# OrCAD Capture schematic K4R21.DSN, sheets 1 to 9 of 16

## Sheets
1 P04: ASPEN - Power: size Custom; title: ASPEN-Power; rev: 1.0; note: K4R2 Main
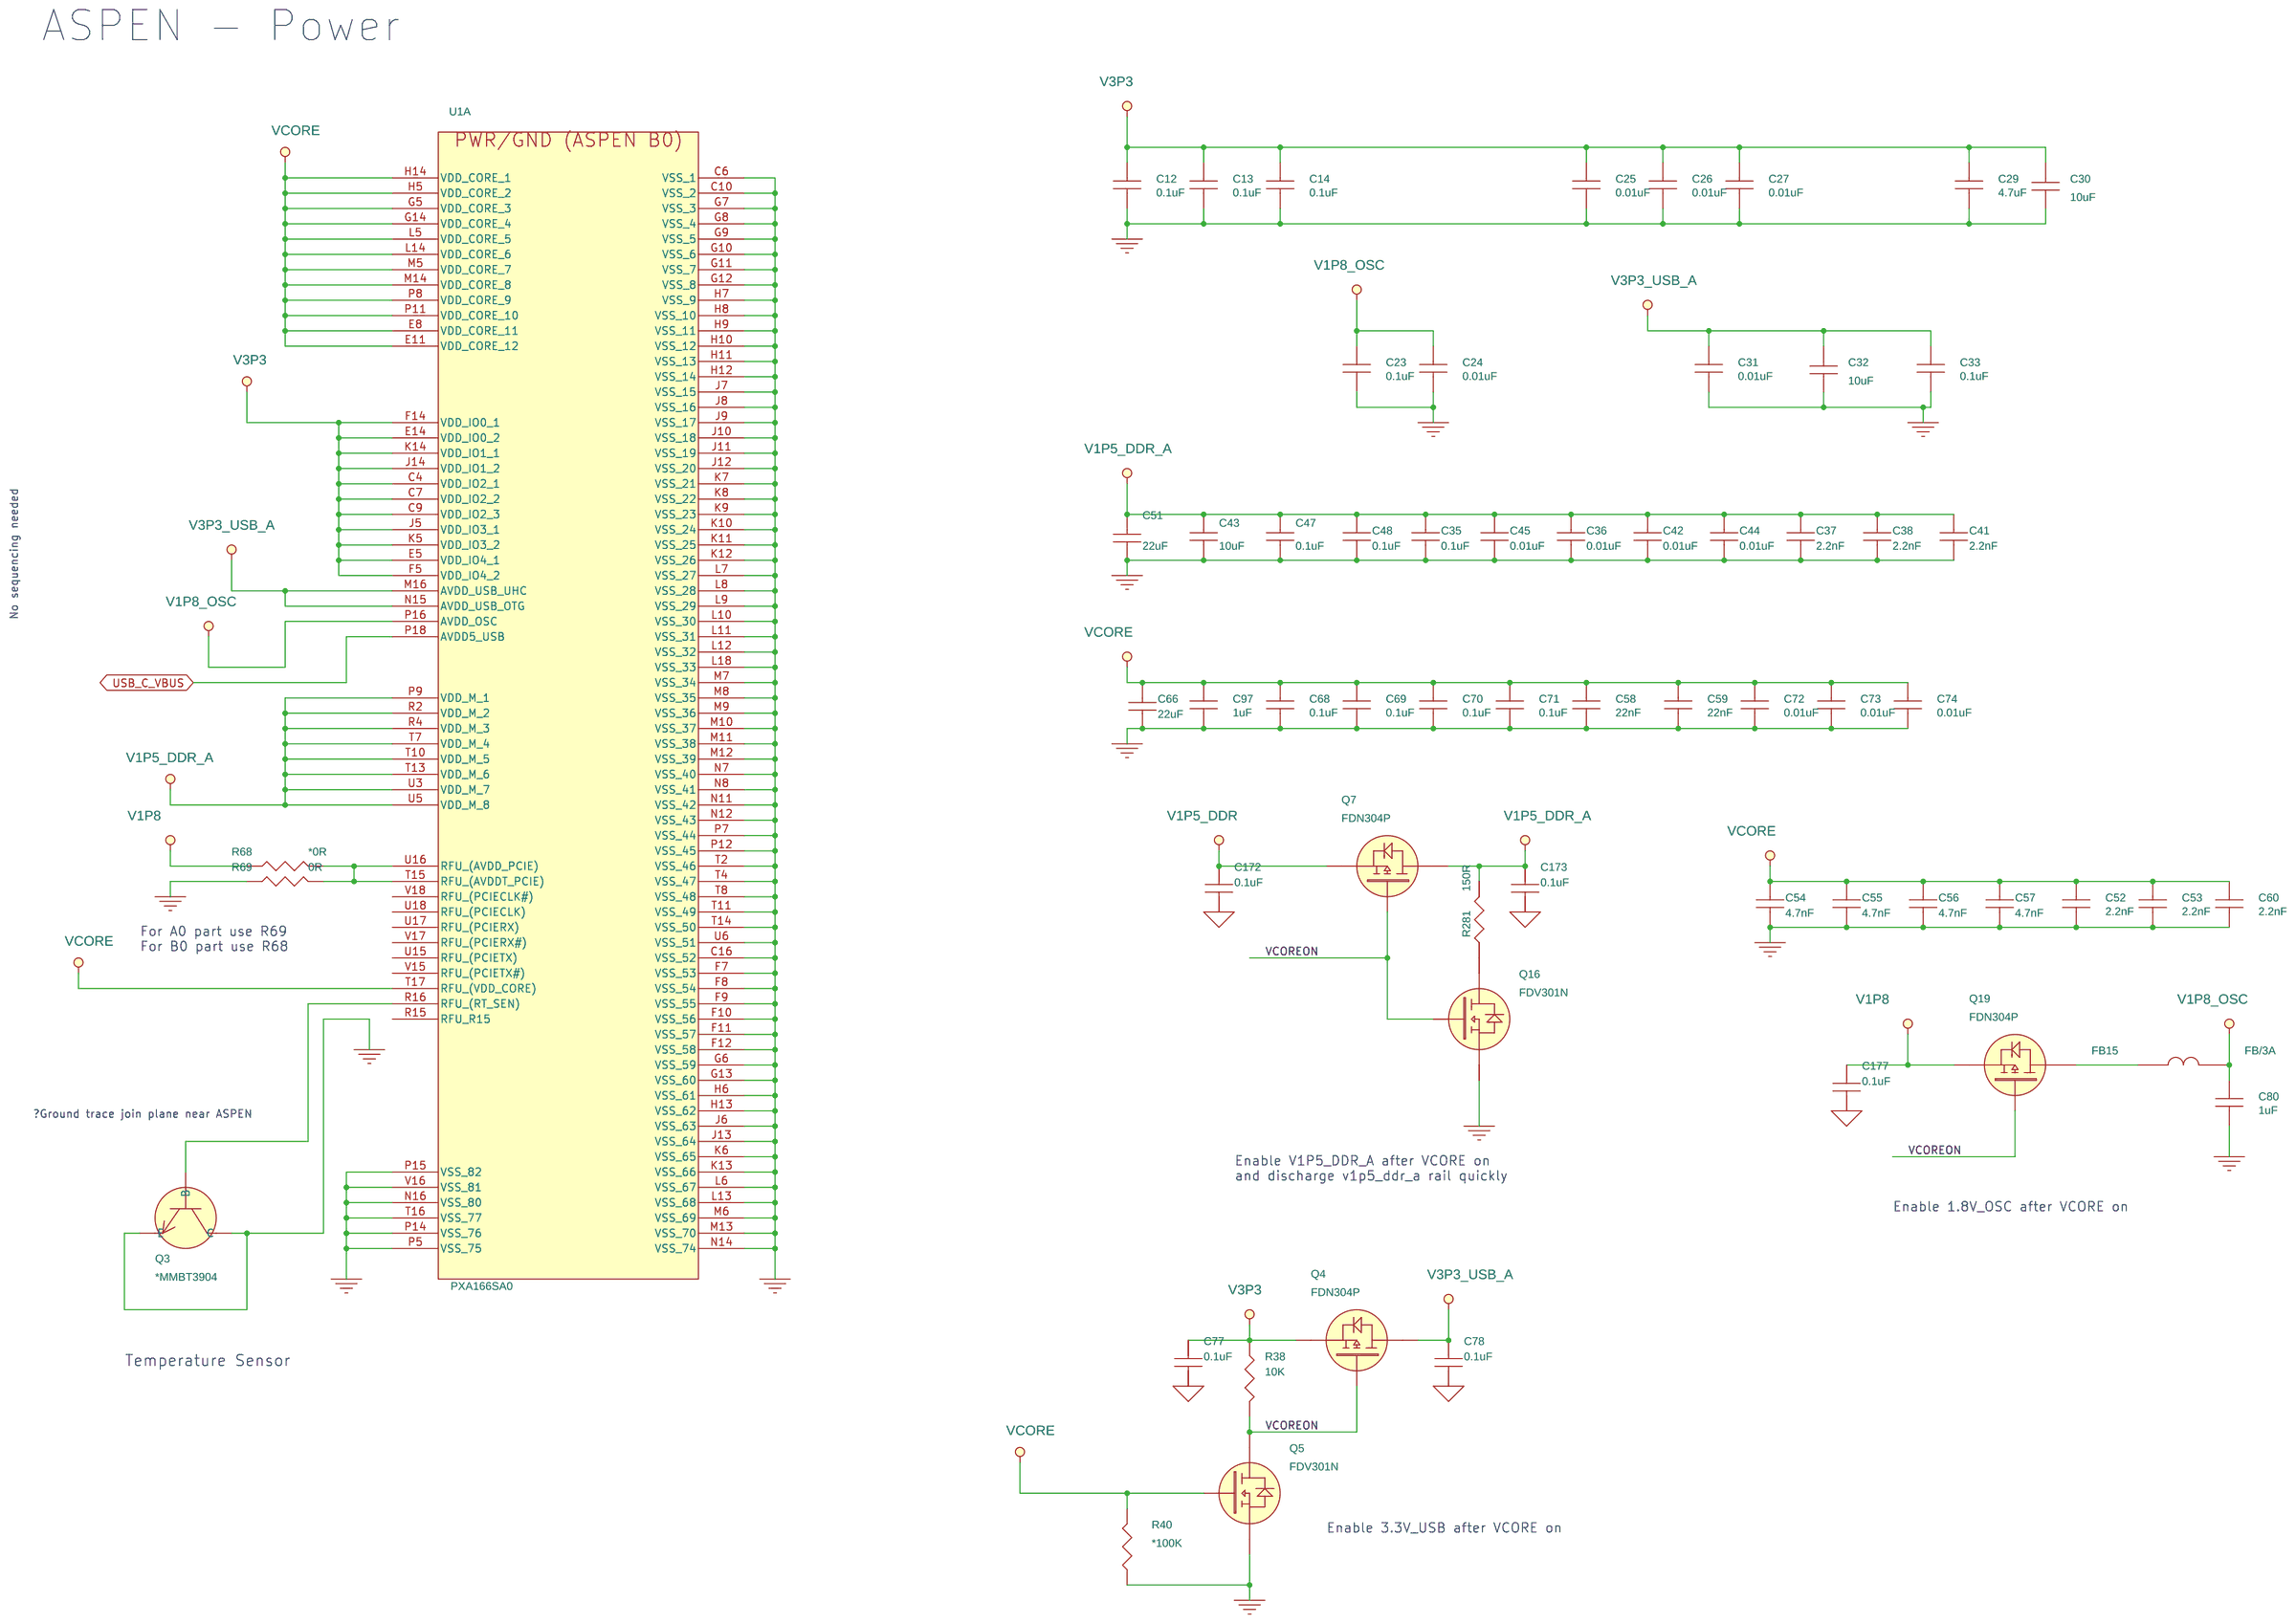
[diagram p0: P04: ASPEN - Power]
2 P06: Wifi 8787: size Custom; title: Wifi
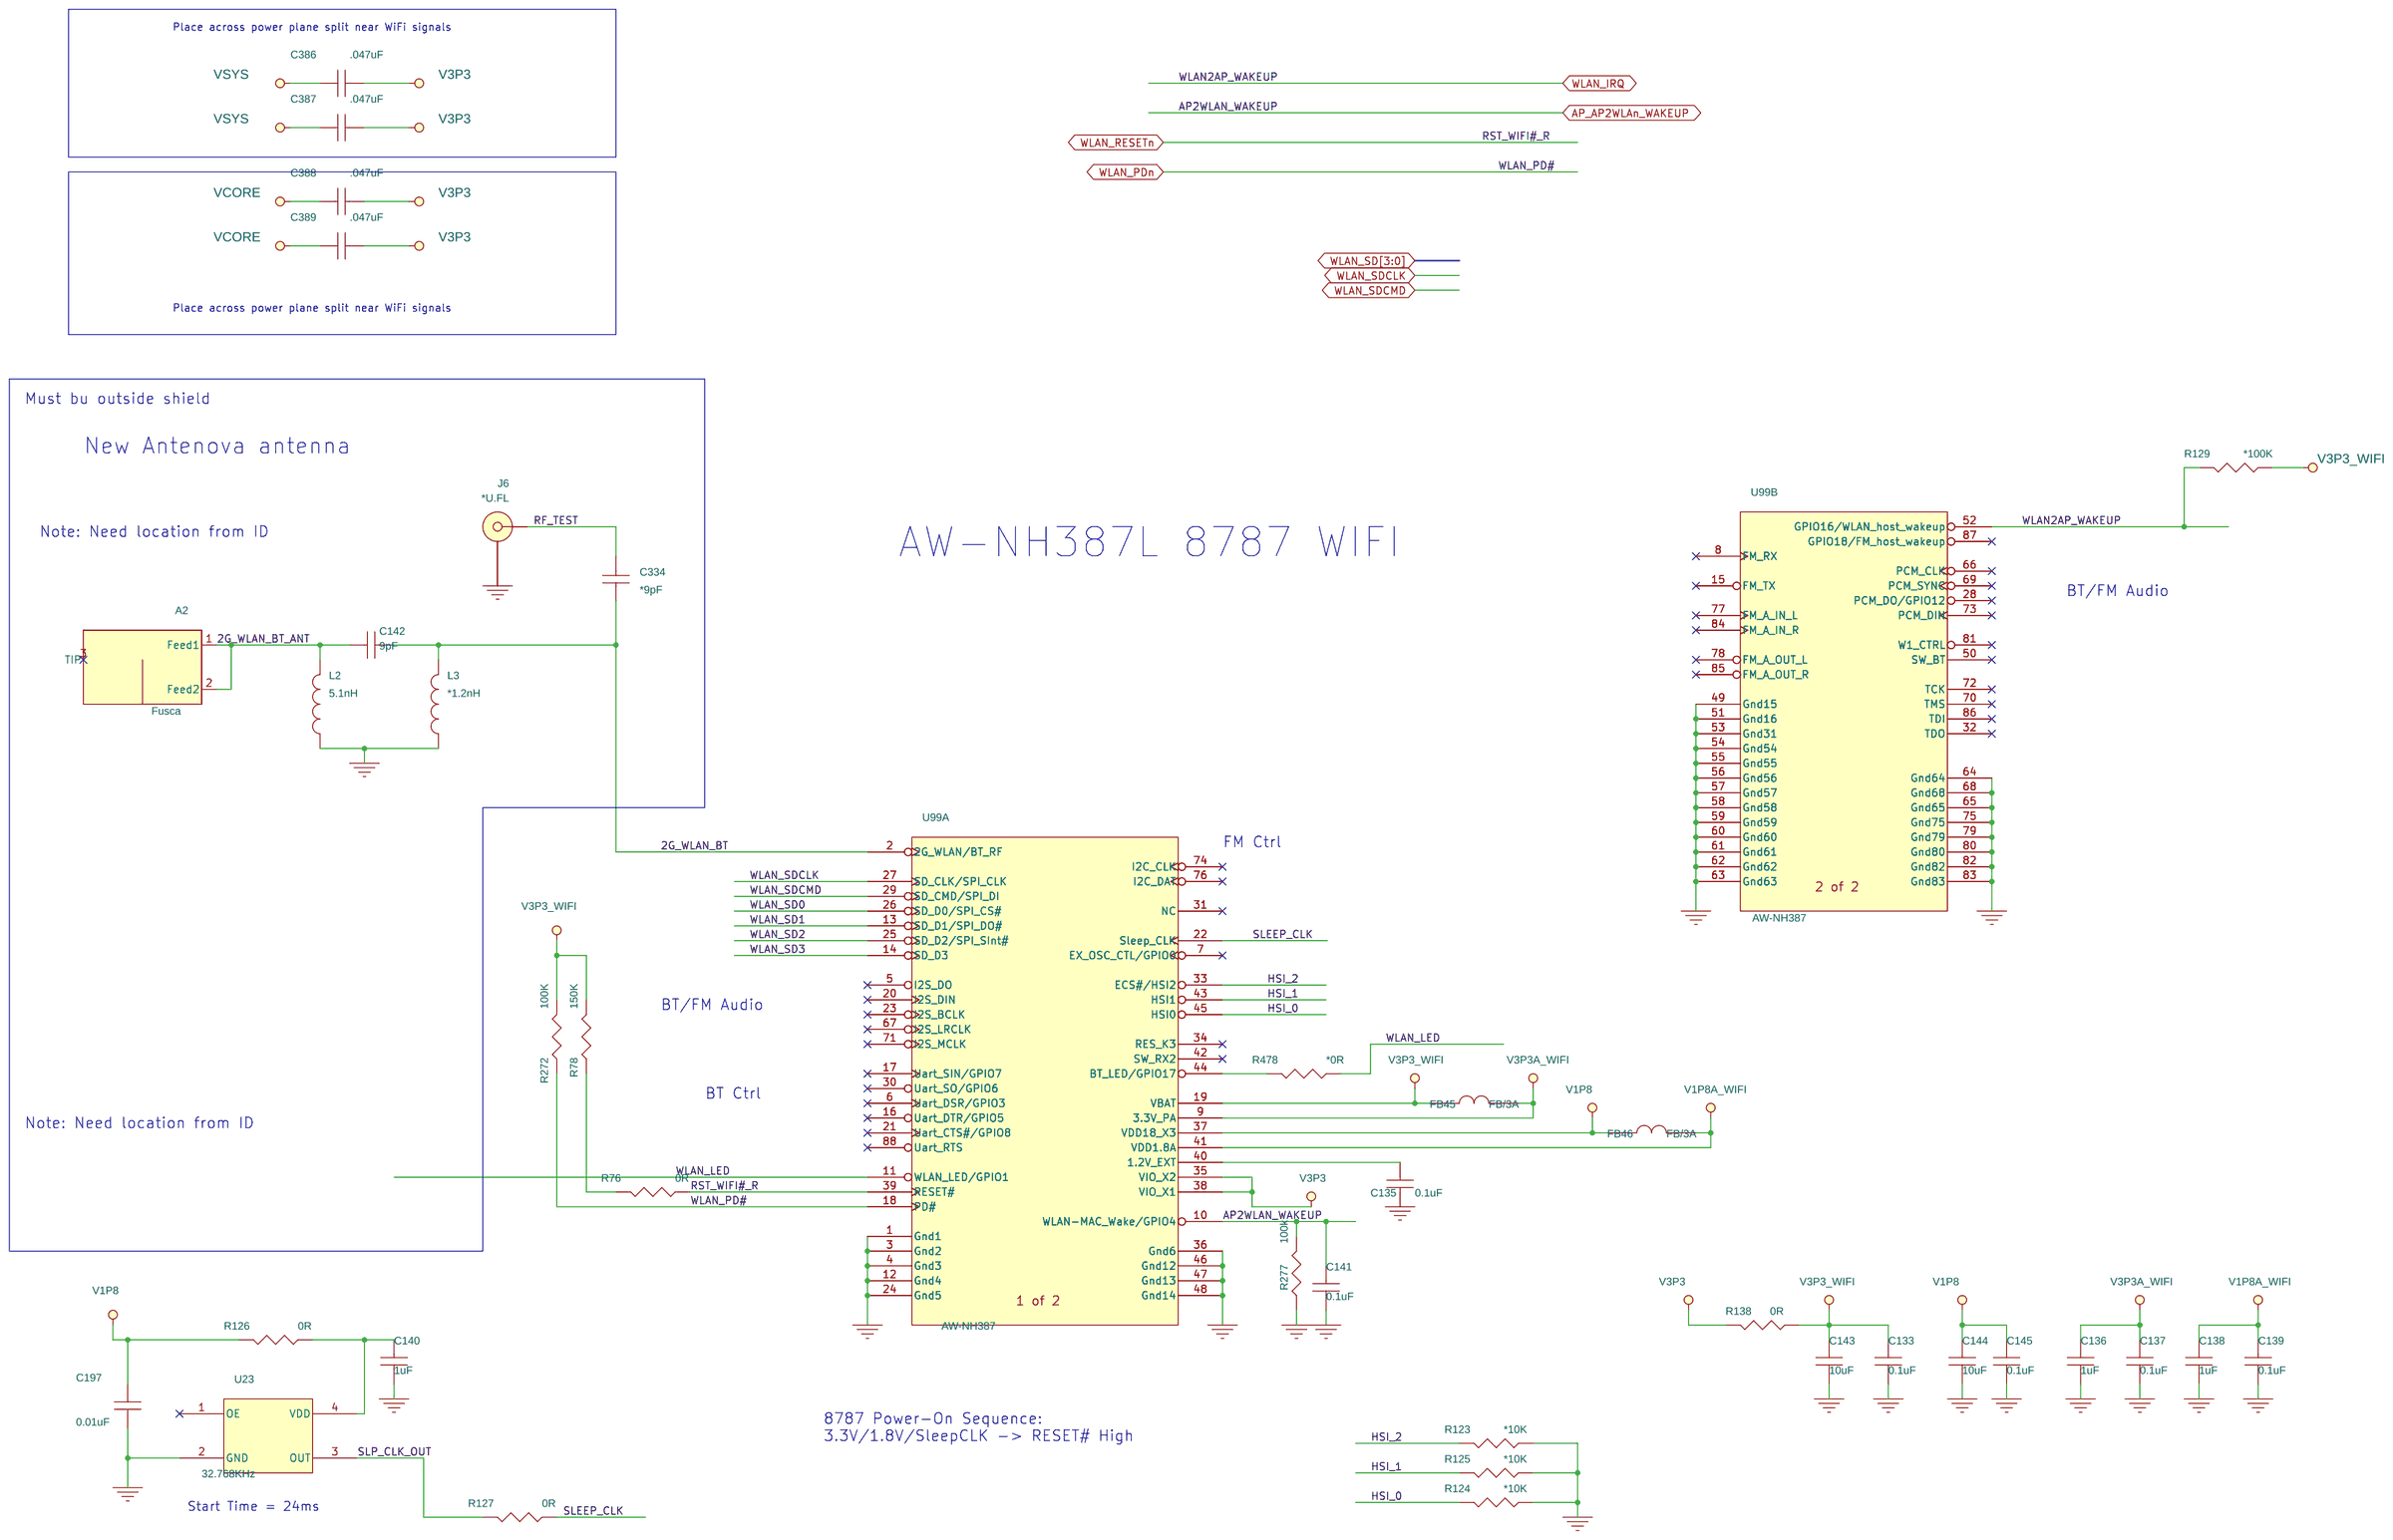
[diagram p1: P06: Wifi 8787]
3 P07: Audio: size Custom; title: Audio; rev: 3.0G
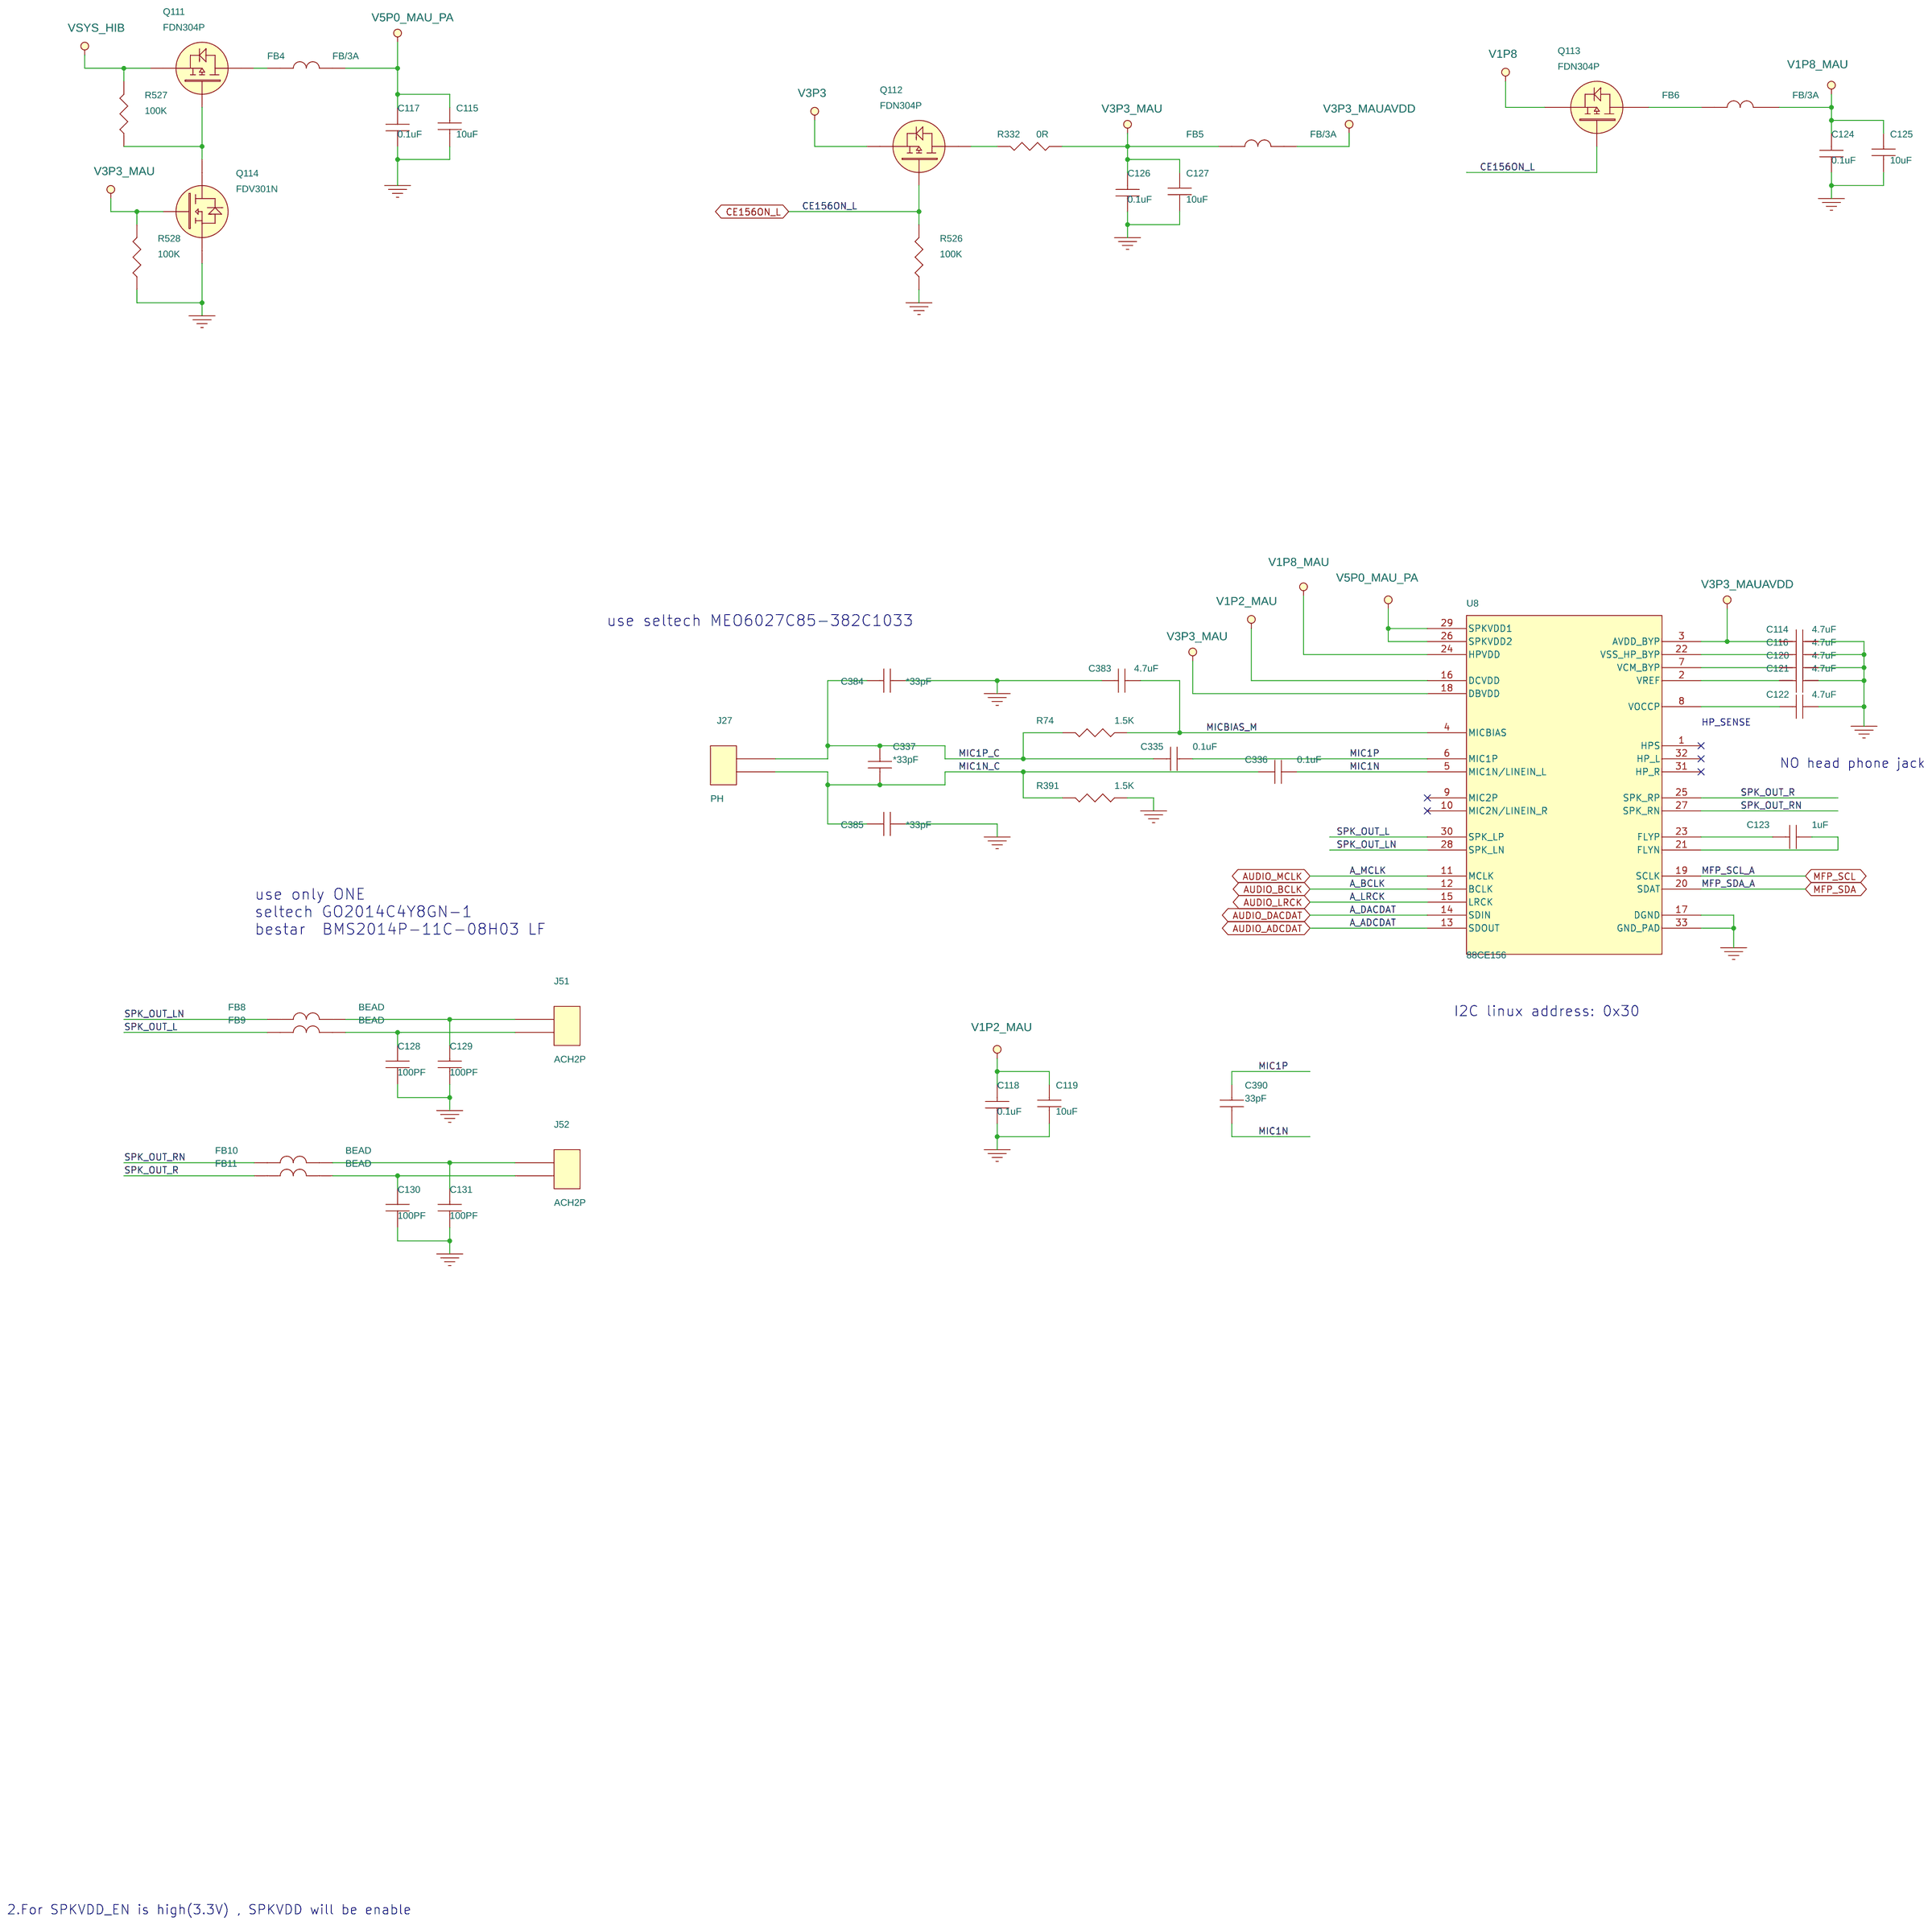
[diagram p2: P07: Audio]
4 P05: DDR3 SPI SD: size Custom; title: DDR3 SDRAM
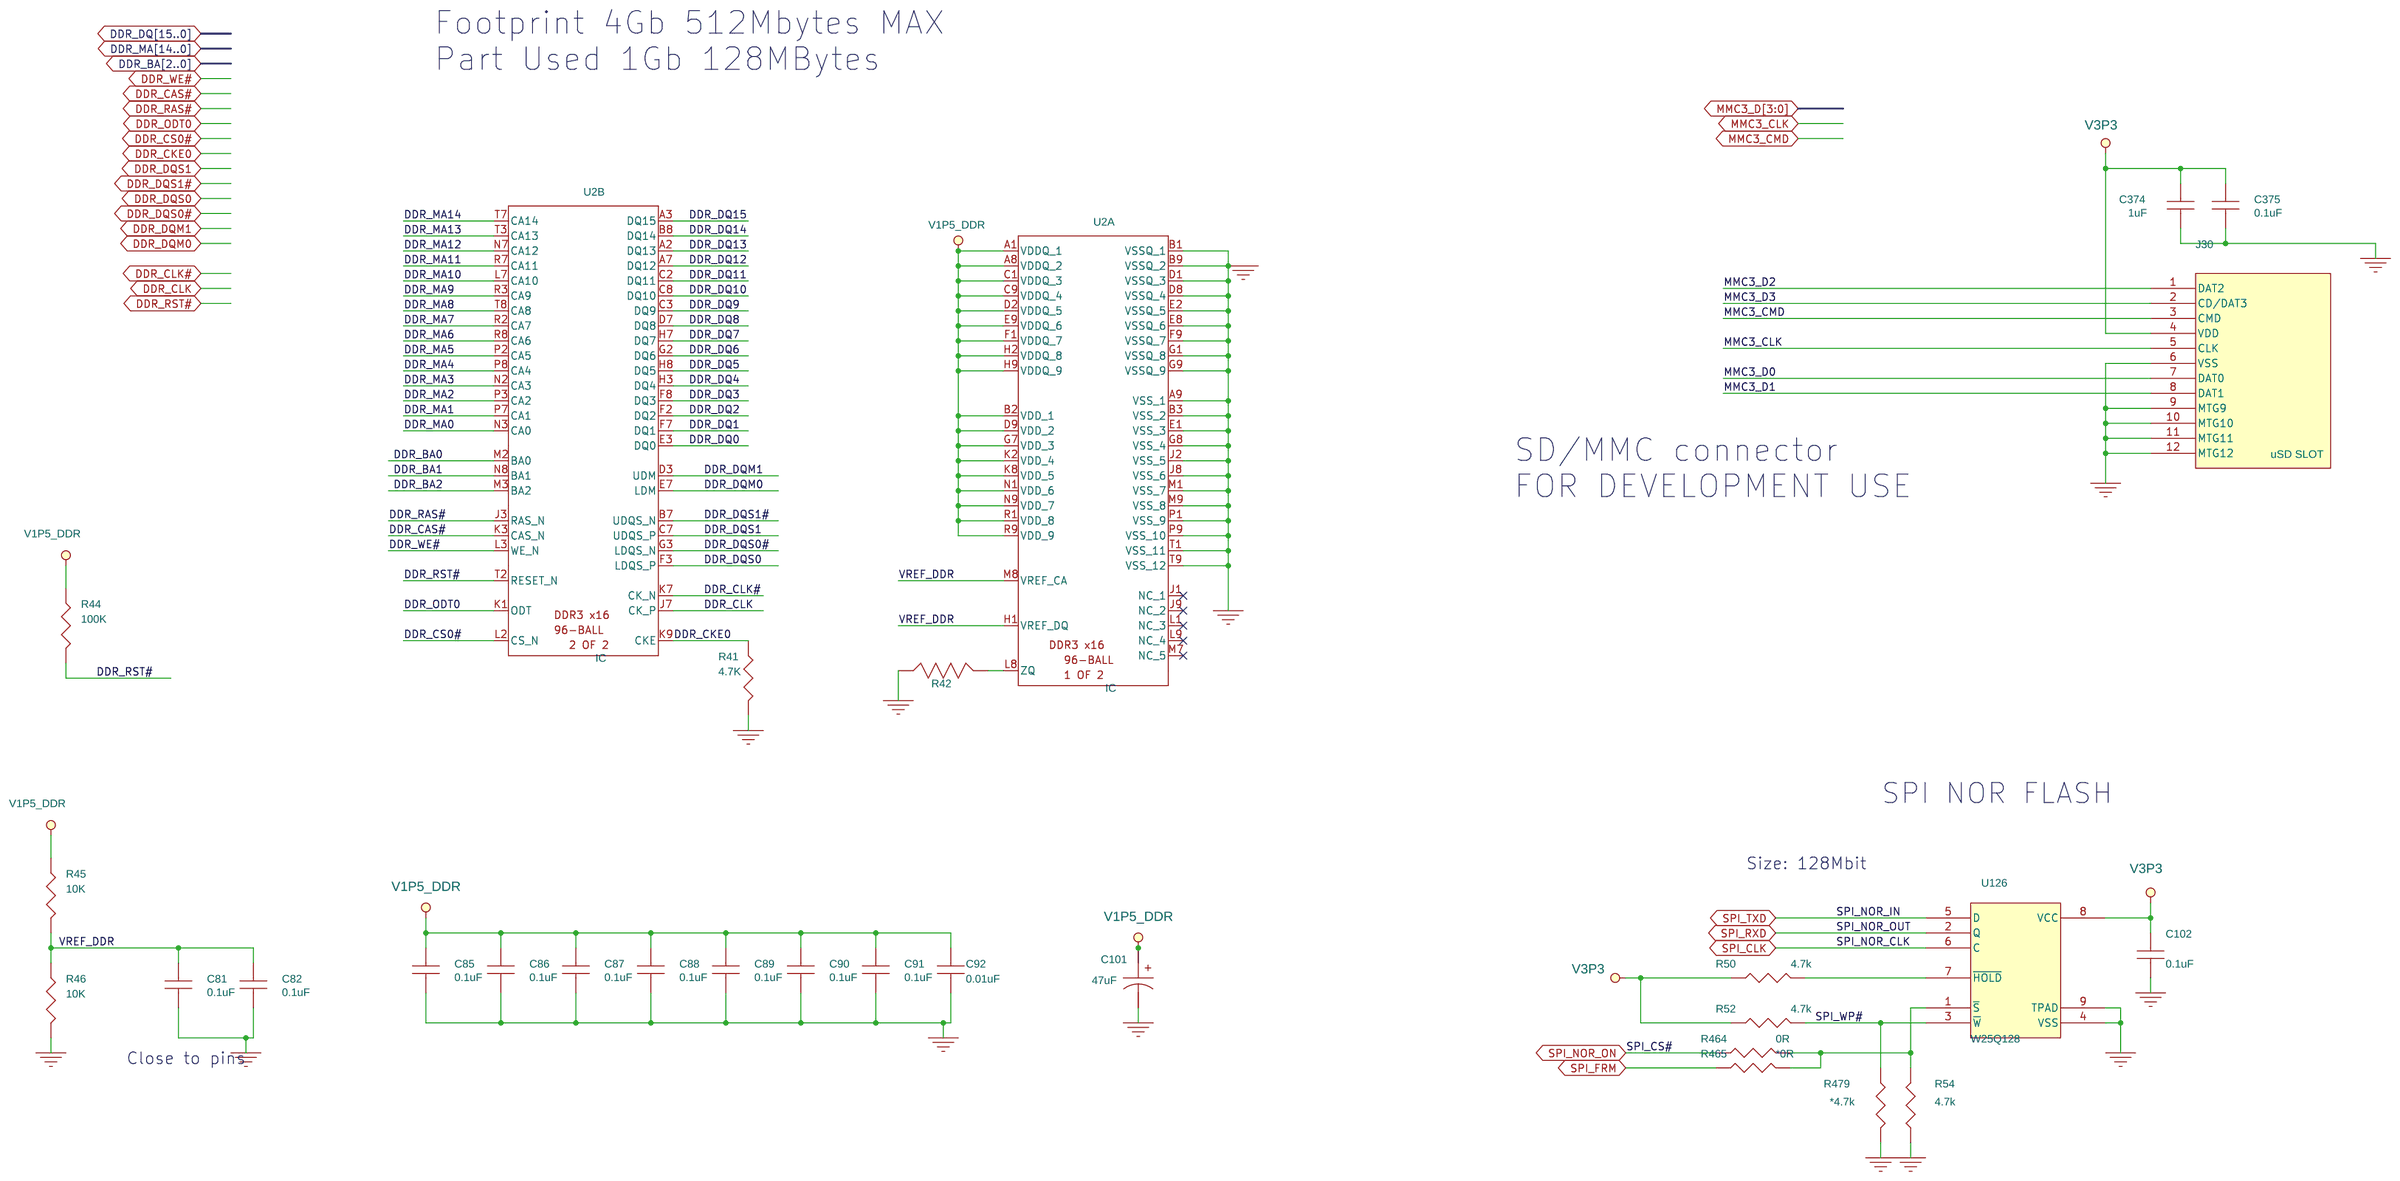
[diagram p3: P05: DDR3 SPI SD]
5 P09: Power architecture: title: Power Distribution diagram; rev: 3.0G
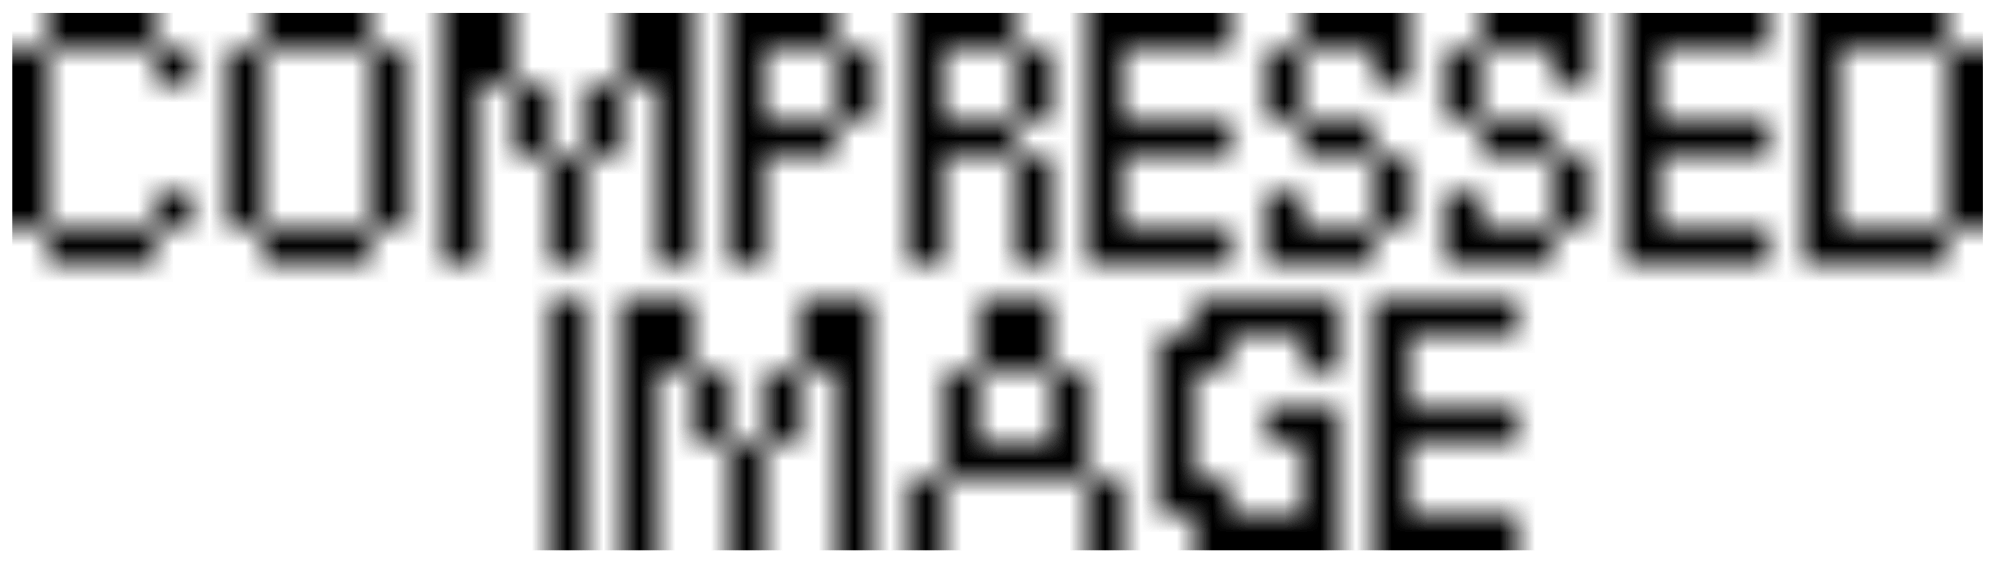
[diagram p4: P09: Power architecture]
6 P01: K4M Block Diagram: title: K4 Main board
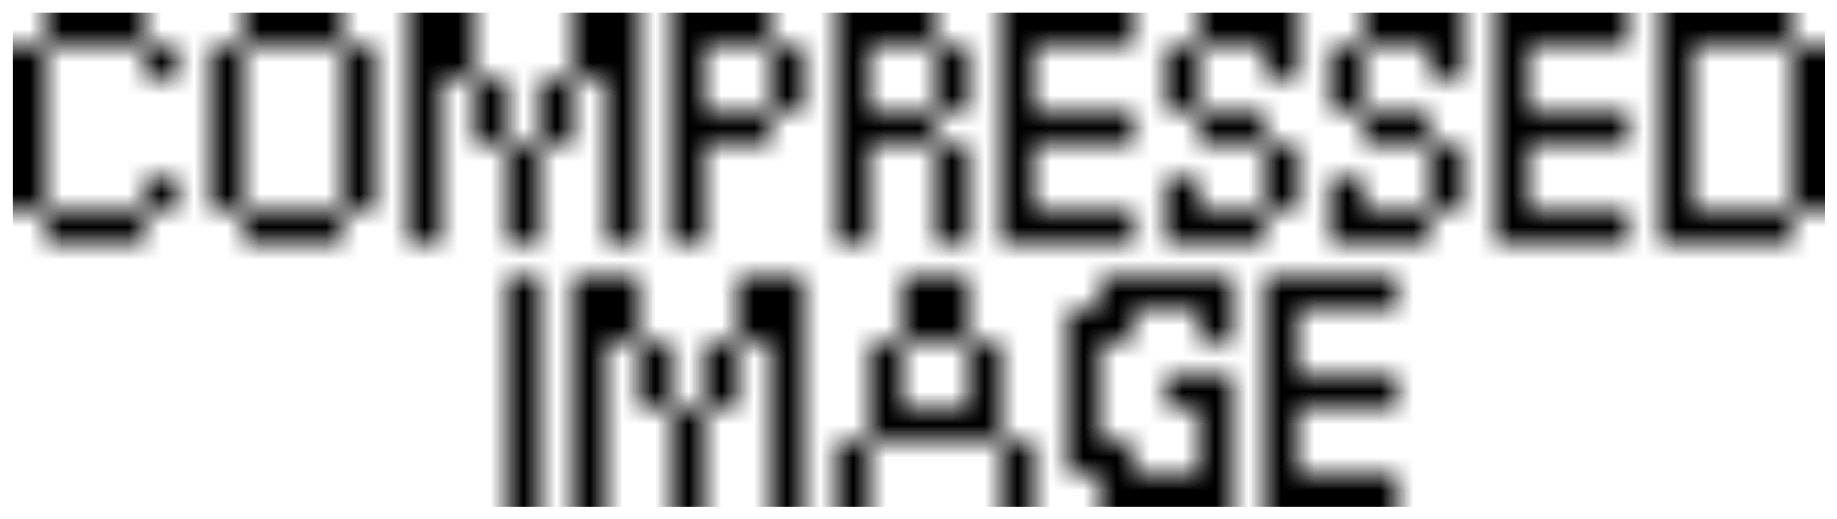
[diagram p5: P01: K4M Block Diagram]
7 P08: LCD connections: size Custom; title: LCD & Touch board conn
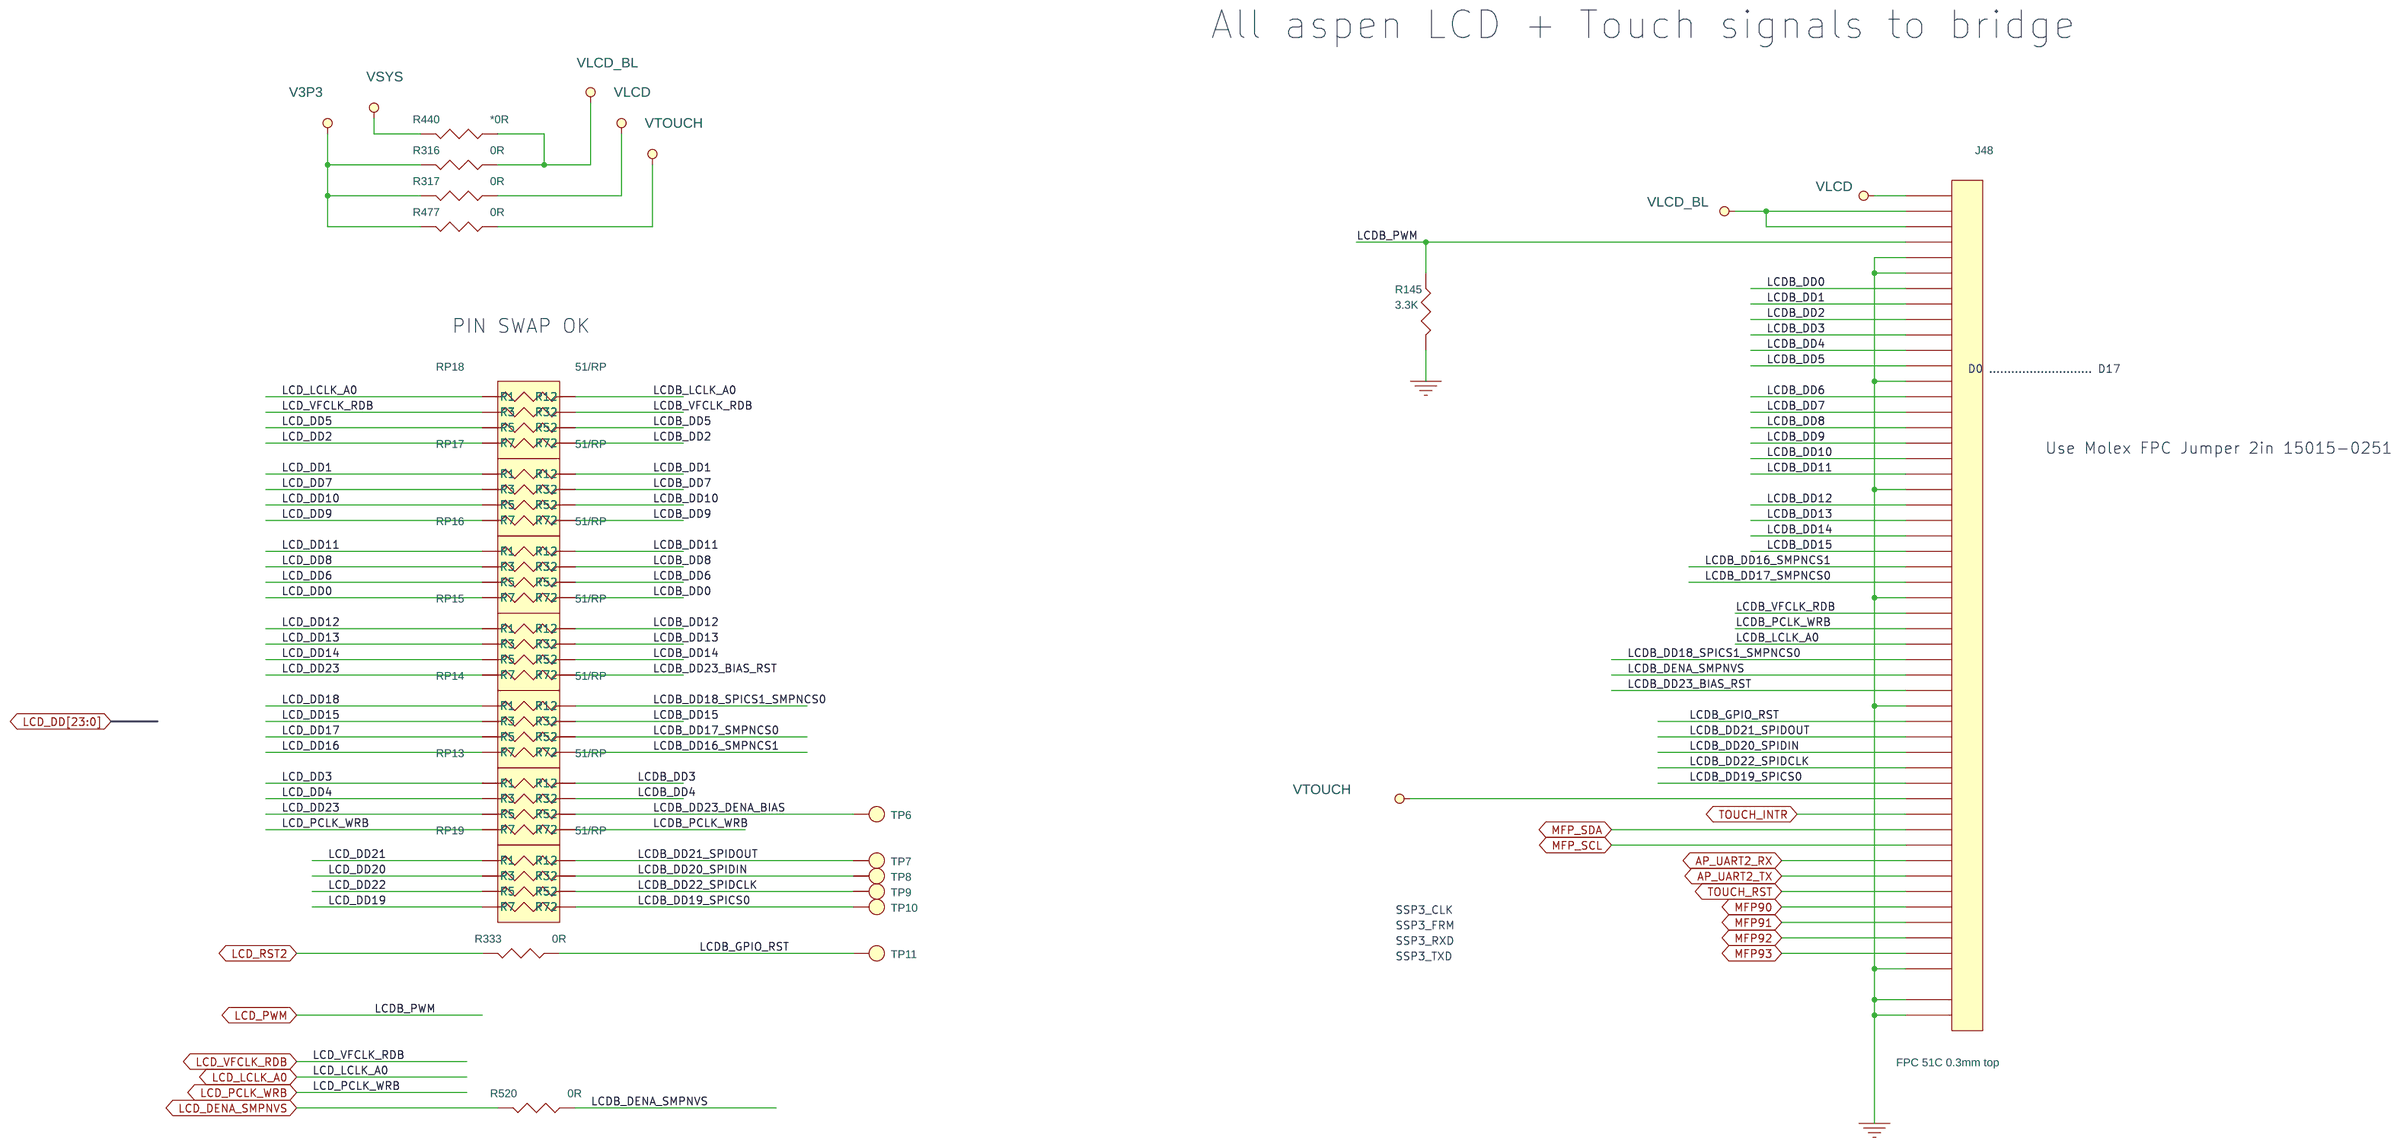
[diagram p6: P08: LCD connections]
8 P02: ASPEN-MEM/USB/LCD: size Custom; title: ASPEN-MEM/FLS/LCD
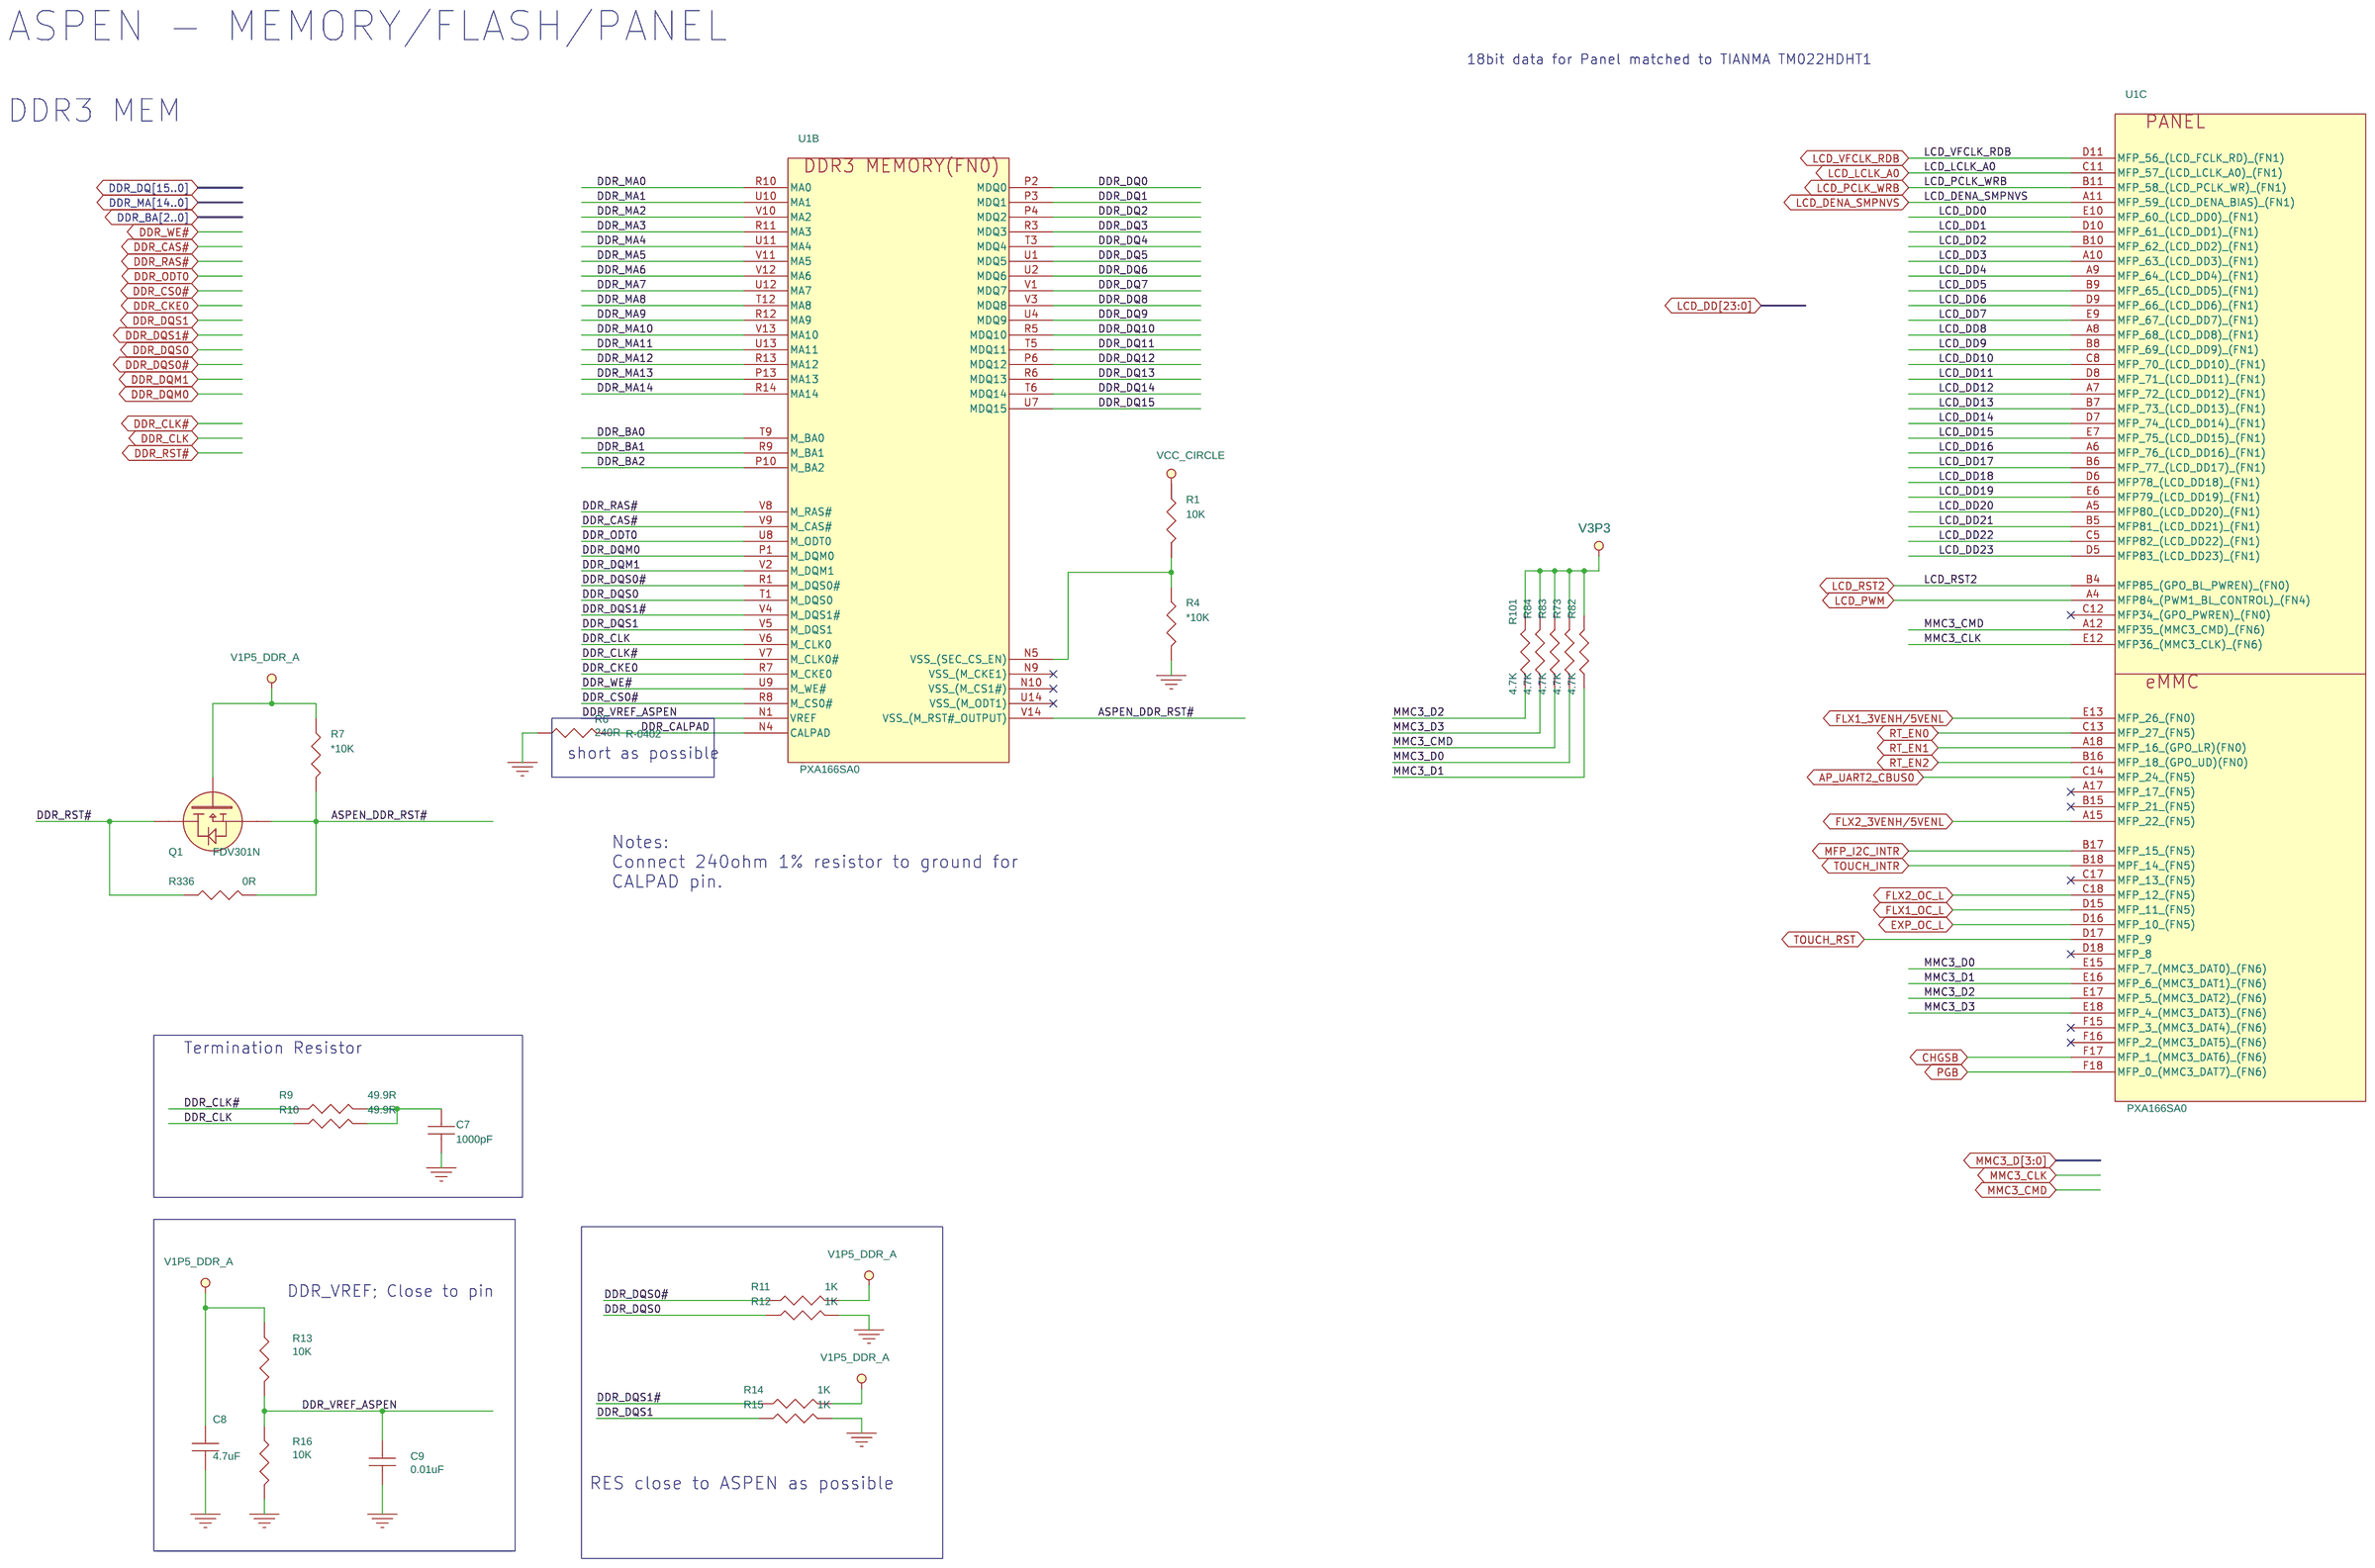
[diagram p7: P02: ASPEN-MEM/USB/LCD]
9 P12: batt, GG, Bst and chgr: size Custom; title: Battery, Charger, Gas Gauge, Boost; rev: 3.0G
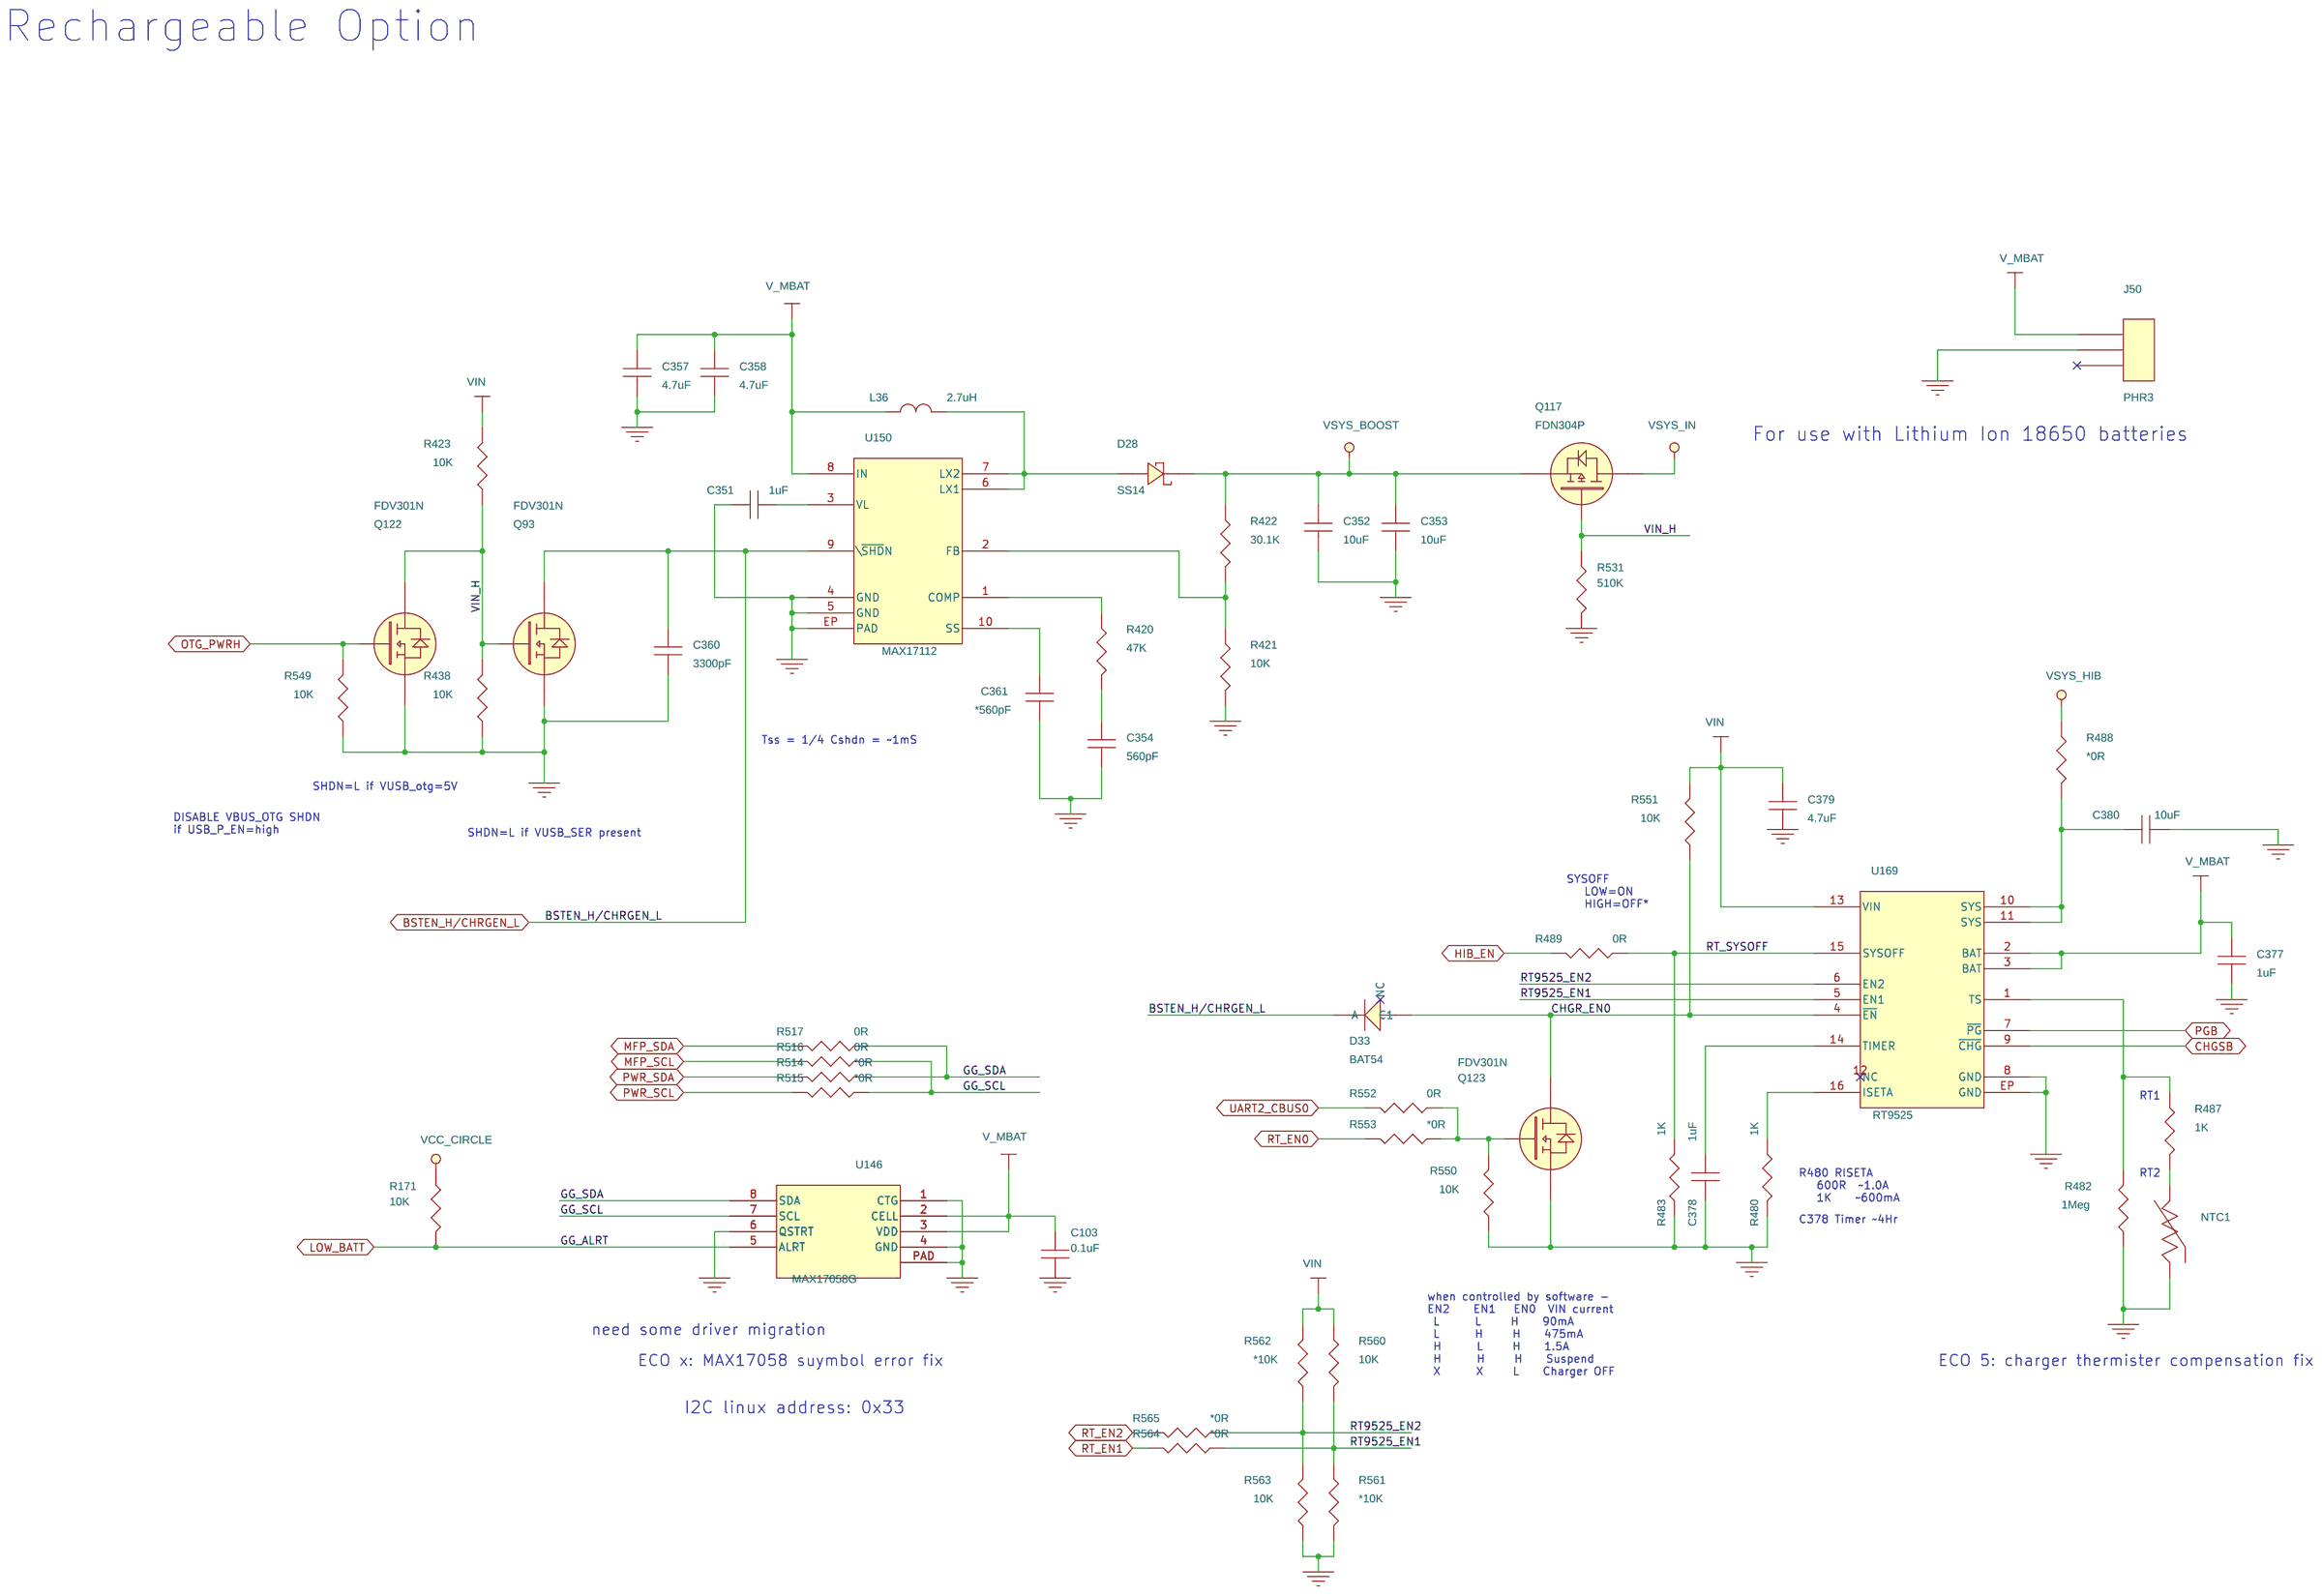
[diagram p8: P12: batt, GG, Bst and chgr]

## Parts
sheet P02: ASPEN-MEM/USB/LCD
C7  1000pF  [C-0402]
C8  4.7uF  [C-0805]
C9  0.01uF  [C-0402]
Q1  FDV301N  [SOT-23a]
R1  10K  [R-0402]
R4  *10K  [R-0402]
R6  240R  [R-0402]
R7  *10K  [R-0402]
R9  49.9R  [R-0402]
R10  49.9R  [R-0402]
R11  1K  [R-0402]
R12  1K  [R-0402]
R13  10K  [R-0402]
R14  1K  [R-0402]
R15  1K  [R-0402]
R16  10K  [R-0402]
R73  4.7K  [R-0402]
R82  4.7K  [R-0402]
R83  4.7K  [R-0402]
R84  4.7K  [R-0402]
R101  4.7K  [R-0402]
R336  0R  [R-0402]
U1  PXA166SA0  [fbga-18x18-320]  (sections A,B,C,D,E,F)
sheet P04: ASPEN - Power
C12  0.1uF  [C-0402]
C13  0.1uF  [C-0402]
C14  0.1uF  [C-0402]
C23  0.1uF  [C-0402]
C24  0.01uF  [C-0402]
C25  0.01uF  [C-0402]
C26  0.01uF  [C-0402]
C27  0.01uF  [C-0402]
C29  4.7uF  [C-0805]
C30  10uF  [C-0402]
C31  0.01uF  [C-0402]
C32  10uF  [C-0402]
C33  0.1uF  [C-0402]
C35  0.1uF  [C-0402]
C36  0.01uF  [C-0402]
C37  2.2nF  [C-0402]
C38  2.2nF  [C-0402]
C41  2.2nF  [C-0402]
C42  0.01uF  [C-0402]
C43  10uF  [C-0402]
C44  0.01uF  [C-0402]
C45  0.01uF  [C-0402]
C47  0.1uF  [C-0402]
C48  0.1uF  [C-0402]
C51  22uF  [C-0603]
C52  2.2nF  [C-0402]
C53  2.2nF  [C-0402]
C54  4.7nF  [C-0402]
C55  4.7nF  [C-0402]
C56  4.7nF  [C-0402]
C57  4.7nF  [C-0402]
C58  22nF  [C-0402]
C59  22nF  [C-0402]
C60  2.2nF  [C-0402]
C66  22uF  [C-0603]
C68  0.1uF  [C-0402]
C69  0.1uF  [C-0402]
C70  0.1uF  [C-0402]
C71  0.1uF  [C-0402]
C72  0.01uF  [C-0402]
C73  0.01uF  [C-0402]
C74  0.01uF  [C-0402]
C77  0.1uF  [C-0402]
C78  0.1uF  [C-0402]
C80  1uF  [C0402]
C97  1uF  [C0402]
C172  0.1uF  [C-0402]
C173  0.1uF  [C-0402]
C177  0.1uF  [C-0402]
FB15  FB/3A  [L-0603]
Q3  *MMBT3904  [SOT23]
Q4  FDN304P  [SOT23-3]
Q5  FDV301N  [SOT-23a]
Q7  FDN304P  [SOT23-3]
Q16  FDV301N  [SOT-23a]
Q19  FDN304P  [SOT23-3]
R38  10K  [R-0402]
R40  *100K  [R-0402]
R68  *0R  [R-0402]
R69  0R  [R-0402]
R281  150R  [R-0402]
sheet P05: DDR3 SPI SD
C81  0.1uF  [C-0402]
C82  0.1uF  [C-0402]
C85  0.1uF  [C-0402]
C86  0.1uF  [C-0402]
C87  0.1uF  [C-0402]
C88  0.1uF  [C-0402]
C89  0.1uF  [C-0402]
C90  0.1uF  [C-0402]
C91  0.1uF  [C-0402]
C92  0.01uF  [C-0402]
C101  47uF  [C-1206]
C102  0.1uF  [C-0402]
C374  1uF  [C0402]
C375  0.1uF  [C-0402]
J30  uSD SLOT  [uSDCARD-push]
R41  4.7K  [R-0402]
R42  240R  [R-0402]
R44  100K  [R-0402]
R45  10K  [R-0402]
R46  10K  [R-0402]
R50  4.7k  [R-0402]
R52  4.7k  [R-0402]
R54  4.7k  [R-0402]
R464  0R  [R-0402]
R465  *0R  [R-0402]
R479  *4.7k  [R-0402]
U2  DDR3_X16_BGA96  [DDR3-96]  (sections A,B)
U126  W25Q128  [qfn-8x6-8s]
sheet P06: Wifi 8787
A2  Fusca  [FUSCA_4x3x1_1mm]
C133  0.1uF  [C-0402]
C135  0.1uF  [C-0402]
C136  1uF  [C0402]
C137  0.1uF  [C-0402]
C138  1uF  [C0402]
C139  0.1uF  [C-0402]
C140  1uF  [C0402]
C141  0.1uF  [C-0402]
C142  9pF  [C-0402]
C143  10uF  [C-0402]
C144  10uF  [C-0402]
C145  0.1uF  [C-0402]
C197  0.01uF  [C-0402]
C334  *9pF  [C-0402]
C386  .047uF  [C-0402]
C387  .047uF  [C-0402]
C388  .047uF  [C-0402]
C389  .047uF  [C-0402]
FB45  FB/3A  [L-0603]
FB46  FB/3A  [L-0603]
J6  *U.FL  [USB_SINGLEBAND_A]
L2  5.1nH  [L-0402]
L3  *1.2nH  [L-0402]
R76  0R  [R-0402]
R78  150K  [R-0402]
R123  *10K  [R-0402]
R124  *10K  [R-0402]
R125  *10K  [R-0402]
R126  0R  [R-0402]
R127  0R  [R-0402]
R129  *100K  [R-0402]
R138  0R  [R-0603]
R272  100K  [R-0402]
R277  100k  [R-0402]
R478  *0R  [R-0402]
U23  32.768KHz  [smy4p-3_2x2_5x1mm]
U99  AW-NH387  [LGA-88]  (sections A,B)
sheet P07: Audio
C114  4.7uF  [C-0805]
C115  10uF  [C-0603]
C116  4.7uF  [C-0805]
C117  0.1uF  [C-0402]
C118  0.1uF  [C-0402]
C119  10uF  [C-0402]
C120  4.7uF  [C-0805]
C121  4.7uF  [C-0805]
C122  4.7uF  [C-0805]
C123  1uF  [C0402]
C124  0.1uF  [C-0402]
C125  10uF  [C-0402]
C126  0.1uF  [C-0402]
C127  10uF  [C-0402]
C128  100PF  [C-0402]
C129  100PF  [C-0402]
C130  100PF  [C-0402]
C131  100PF  [C-0402]
C335  0.1uF  [C-0402]
C336  0.1uF  [C-0402]
C337  *33pF  [C-0402]
C383  4.7uF  [C-0805]
C384  *33pF  [C-0402]
C385  *33pF  [C-0402]
C390  33pF  [C-0402]
FB4  FB/3A  [L-0603]
FB5  FB/3A  [L-0603]
FB6  FB/3A  [L-0603]
FB8  BEAD  [L-0603]
FB9  BEAD  [L-0603]
FB10  BEAD  [L-0603]
FB11  BEAD  [L-0603]
J27  PH  [JST_PH2P_2MM]
J51  ACH2P  [JST_ACHSS_2P1_2MM]
J52  ACH2P  [JST_ACHSS_2P1_2MM]
Q111  FDN304P  [SOT23-3]
Q112  FDN304P  [SOT23-3]
Q113  FDN304P  [SOT23-3]
Q114  FDV301N  [SOT-23a]
R74  1.5K  [R-0402]
R332  0R  [R-0603]
R391  1.5K  [R-0402]
R526  100K  [R-0402]
R527  100K  [R-0402]
R528  100K  [R-0402]
U8  88CE156  [QFN32p-0_5-5X5X1MM]
sheet P08: LCD connections
J48  FPC 51C 0.3mm top  [FH35_51_0_3MM]
R145  3.3K  [R-0402]
R316  0R  [R-0402]
R317  0R  [R-0402]
R333  0R  [R-0402]
R440  *0R  [R-0402]
R477  0R  [R-0402]
R520  0R  [R-0402]
RP13  51/RP  [EXB28V]
RP14  51/RP  [EXB28V]
RP15  51/RP  [EXB28V]
RP16  51/RP  [EXB28V]
RP17  51/RP  [EXB28V]
RP18  51/RP  [EXB28V]
RP19  51/RP  [EXB28V]
TP6  *T_POINT  [TP]
TP7  *T_POINT  [TP]
TP8  *T_POINT  [TP]
TP9  *T_POINT  [TP]
TP10  *T_POINT  [TP]
TP11  *T_POINT  [TP]
sheet P12: batt, GG, Bst and chgr
C103  0.1uF  [C-0402]
C351  1uF  [C0402]
C352  10uF  [C-0603]
C353  10uF  [C-0603]
C354  560pF  [C-0402]
C357  4.7uF  [C-0603]
C358  4.7uF  [C-0603]
C360  3300pF  [C-0402]
C361  *560pF  [C-0402]
C377  1uF  [C0402]
C378  1uF  [C0402]
C379  4.7uF  [C-0603]
C380  10uF  [C-0603]
D28  SS14  [SMA]
D33  BAT54  [sot23]
J50  PHR3  [JST_PHR3P_2mm]
L36  2.7uH  [SDR0302]
NTC1  10K  [R-0402]
Q93  FDV301N  [SOT-23a]
Q117  FDN304P  [SOT23-3]
Q122  FDV301N  [SOT-23a]
Q123  FDV301N  [SOT-23a]
R171  10K  [R0402]
R420  47K  [R-0402]
R421  10K  [R-0402]
R422  30.1K  [R-0402]
R423  10K  [R-0402]
R438  10K  [R-0402]
R480  1K  [R-0402]
R482  1Meg  [R-0402]
R483  1K  [R-0402]
R487  1K  [R-0402]
R488  *0R  [R-0603]
R489  0R  [R-0402]
R514  *0R  [R-0402]
R515  *0R  [R-0402]
R516  0R  [R-0402]
R517  0R  [R-0402]
R531  510K  [R-0402]
R549  10K  [R-0402]
R550  10K  [R-0402]
R551  10K  [R-0402]
R552  0R  [R-0402]
R553  *0R  [R-0402]
R560  10K  [R-0402]
R561  *10K  [R-0402]
R562  *10K  [R-0402]
R563  10K  [R-0402]
R564  *0R  [R-0402]
R565  *0R  [R-0402]
U146  MAX17058G  [TDFN8]
U150  MAX17112  [TDFN10EP]
U169  RT9525  [WQFN16EP]

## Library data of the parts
C7 = CAP_NP_1: Desc: CAP 1nF 10% 0402 25V X7R; Part Num: C0402S102K3RACTU; Vendor: kemet; mfg: Kemet; mfg_pn: C0402S102K3RACTU
C8 C114 C116 C120-C122 C383 = CAP_NP_0: Desc: CAP 4.7uF 10% 0805 25V X5R; Part Num: C0805C475K3PACTU; Vendor: kemet
C9 = CAP_NP_0: Desc: CAP CER 10000PF 16V 10% X7R 0402; Mfr: Murata; Part Num: GRM155R71C103KA01D; Vendor: Murata
Q1 Q5 Q16 Q93 Q114 Q122 Q123 = NMOS3: Desc: MOSFET N-CH 25V 220MA SOT-23; Vendor: FAIRCHILD
R1 R4 R7 = RESISTOR: Desc: RES 10K OHM 1/10W 5% 0402 SMD; Part Num: ERJ-2GEJ103X; Vendor: Panasonic
R6 = Res_0: Desc: RES 240 OHM 1/10W 1% 0402 SMD; Mfr: Generic; Part Num: ERJ-2RKF2400X; Vendor: Panasonic
R9 R10 = Res_0: Desc: RES 49.9 OHM 1/10W 1% 0402 SMD; Mfr: Generic; Part Num: ERJ-2RKF49R9X; Vendor: Panasonic
R11 R12 R14 R15 = Res_0: Desc: RES 1K OHM 1/10W 1% 0402 SMD; Mfr: Generic; Part Num: ERJ-2RKF1001X; Vendor: Panasonic; d: RES 1K OHM 1/10W 1% 0402 SMD
R13 R16 R45 R46 R123-R125 = Res_0: Desc: RES 10K OHM 1/10W 5% 0402 SMD; Mfr: Generic; Part Num: ERJ-2GEJ103X; Vendor: Panasonic
R50 R52 R54 R73 R82 R101 R479 = Res_0: Desc: RES 4.7K OHM 1/10W 5% 0402 SMD; Part Num: ERJ-2GEJ472X; Vendor: Panasonic
R83 R84 = Res_0: Desc: RES 4.7K OHM 1/10W 5% 0402 SMD; Part Num: ERJ-2GEJ472X; Part Number: R4720402; Vendor: Panasonic
R316 R317 R333 R336 R440 R477 R520 = Res_0: Desc: RES 0.0 OHM 1/10W 0402 SMD; Mfr: Generic; Part Num: ERJ-2GE0R00X; Vendor: Panasonic; ccc: RES 0.0 OHM 1/10W 0402 SMD
U1 = PXA168_1: Desc: IC App Processor SOC; Part Num: 88AP166SA0-BJD2C008; Vendor: Marvell
C12-C14 C23 C33 C35 C47 C48 C68-C71 C375 = CAP_NP_1: Desc: CAP CER .10UF 10V X7R 0402; Part Num: C1005X7R1A104K; Vendor: TDK
C24-C27 C31 C36 C42 C44 C45 C72-C74 = CAP_NP_1: Desc: CAP CER 10000PF 16V 10% X7R 0402; Mfr: Murata; Part Num: GRM155R71C103KA01D; Vendor: Murata
C29 = CAP_NP_1: Desc: CAP 4.7uF 10% 0805 25V X5R; Part Num: C0805C475K3PACTU; Vendor: kemet
C30 C32 C43 C143 C144 = CAP_NP_0: Desc: CAP CER 10UF 6.3V 20% X5R 0402; Part Num: C1005X5R0J106M050BC; Vendor: TDK
C37 C38 C41 C52 C53 C60 = CAP_NP_1: Desc: CAP CER 2200PF 25V 10% X7R 0402; Part Num: 04023C222KAT2A; Vendor: avx; mfg: avx
C51 C66 = CAP_NP_0: Desc: CAP CER 22UF 4V 20% X5R 0603; Part Num: AMK107BJ226MA-T; Vendor: Taiyo
C54-C57 = CAP_NP_1: Desc: CAP CER 4700PF 25V 10% X7R 0402; Part Num: 04023C472KAT2A; Vendor: AVX; mfg_pn: 04023C472KAT2A
C58 C59 = CAP_NP_1: Desc: CAP 22nF 10% 0402 10V X7R; Part Num: VJ0402Y223JXQCW1BC; Vendor: vishay; mfg: vishay; mfg_pn: VJ0402Y223JXQCW1BC
C77 C78 C172 C173 C177 = CAP_NP_2: Desc: CAP CER .10UF 10V X7R 0402; Part Num: C1005X7R1A104K; Vendor: TDK; mfg: TDK; mfg_pn: C1005X7R1A104K
C80 C97 C374 = CAP_NP: Desc: CAP CER 1UF 10V 10% X5R 0402; Part Num: C1005X5R1A105K050BB; Vendor: TDK; ccc: CAP CER 1UF 10V 10% X5R 0402
FB4-FB6 FB15 FB45 FB46 = FERRITE_BEAD_0: Desc: FERRITE CHIP 120 OHM 3000MA 0603; Part Num: BLM18KG121TN1; Vendor: Murata
Q3 = NPN: Desc: Transistor NPN MMBT3904; Part Num: MMBT3904LT1G; Vendor: On Semi
Q4 Q7 Q19 Q111-Q113 Q117 = PMOS3: Desc: MOSFET P-CH 20V 2.4A SSOT3; Vendor: FAIRCHILD
R38 = R_0: Desc: RES 10K OHM 1/10W 5% 0402 SMD; Mfr: Generic; Part Num: ERJ-2GEJ103X; Vendor: Panasonic
R40 R526-R528 = R_0: RES 100K OHM 1/20W 5% 0201 SMD; Desc: RES 100K OHM 1/16W 5% 0402 SMD; Mfr: Generic; Part Num: CRCW0402100KJNED; Vendor: Vishay
R68 R69 R464 R465 = Res_0: Desc: RES 0.0 OHM 1/10W 0402 SMD; Mfr: Generic; Part Num: ERJ-2GE0R00X; Vendor: Panasonic
R281 = Res_0: Desc: RES 150 OHM 1/16W 1% 0402 SMD; Part Num: MCR01MZPF1500; Vendor: Rohm
C81 C82 C85-C91 = CAP_NP_1: Desc: CAP CER .10UF 10V X7R 0402; Part Num: C1005X7R1A104K; Vendor: TDK; mfg: TDK; mfg_pn: C1005X7R1A104K
C92 = CAP_NP_1: Desc: CAP CER 10000PF 16V 10% X7R 0402; Mfr: Murata; Part Num: GRM155R71C103KA01D; Vendor: Murata; mfg: Murata; mfg_pn: GRM155R71C103KA01D
C101 = CAPACITOR_POL_0: Desc: CAP CER 47UF 4V X6S 1206; Part Num: GRM31CC80G476ME19L; Vendor: Murata
C102 C117 C118 C124 C126 C133 C135 C137 C139 C141 C145 C335 C336 = CAP_NP_0: Desc: CAP CER .10UF 10V X7R 0402; Part Num: C1005X7R1A104K; Vendor: TDK
J30 = uSDCARD: Desc: CONN MINI MICRO-SD 8PIN PCB GOLD; OPTION: DBG; Part Num: 101-00660-68-6; Vendor: Amphenol
R41 = Res_0: Desc: RES 4.7K OHM 1/10W 5% 0402 SMD; Mfr: Generic; Part Num: ERJ-2GEJ472X; Vendor: Panasonic
R42 = RES: $LOCATION: R169; $SEC: 1; $TOLERENCE: ?; CDS_LIB: resistors; CDS_LOCATION: R169; CDS_SEC: 1; DRAWING: @ASPENITE_LIB.ASPENITE(SCH_1):PAGE21; Desc: RES 240 OHM 1/10W 1% 0402 SMD; LOCATION: R169; MATERIAL: CH; PACK_TYPE: RES0402; PART_NUMBER: R00017-001; PATH: I450; PHYS_PAGE: 6; Part Num: ERJ-2RKF2400X; ROT: 2; SEC: 1; TOL: 5%; VER: 1; Vendor: Panasonic; WATTAGE: 1/16W; XY: (3175,2075)
R44 R129 = Res_0: Desc: RES 100K OHM 1/16W 5% 0402 SMD; Mfr: Generic; Part Num: CRCW0402100KJNED; Vendor: Vishay
U2 = DDR3_X16_BGA96: Desc: IC DDR3 1Gbit-64Mx16; MATERIAL: IC; Part Num: NT5CB64M16FP-CF; Vendor: Nanya
U126 = M25P64-MLP8: Desc: Flash Mem Serial-SPI 3.3V 128M-Bit 16M x 8 8ns 8-Pin VDFPN EP; Part Num: W25Q128FVEIG; Vendor: Winbond
A2 = Fusca
C123 C136 C138 C140 = CAP_NP_0: Desc: CAP CER 1UF 10V 10% X5R 0402; Part Num: C1005X5R1A105K050BB; Vendor: TDK; ccc: CAP CER 1UF 10V 10% X5R 0402
C142 C334 = CAP_NP_0: Desc: CAP CER 9PF 50V C0G 0402; Part Num: GRM1555C1H9R0DZ01D; Tolerance: 10%; Vendor: Murata
C197 = CAP_NP: Desc: CAP CER 10000PF 16V 10% X7R 0402; Mfr: Murata; Part Num: GRM155R71C103KA01D; Vendor: Murata
C386-C389 = CAP_NP: Desc: CAP CER 0.047UF 16V 10% X7R 0402; Mfr: Murata; Part Num: C1005X7R1C473K050BC; Vendor: TDK
J6 = HIROSE_U.FL-R-SMT: Desc: Conn coax rf; Manufacturer: Hirose; Part Num: U.FL-R-SMT; Vendor: Hirose
L2 = INDUCTOR: Desc: INDUCTOR 5.1NH 300MA 0402; Part Num: LQG15HS5N1S02D; Vendor: Murata
L3 = INDUCTOR: Desc: IND 1.2nH 300mA 0.12ohm Q=8 SMD 0402 GP; Part Num: ILC0402ER1N2S; Vendor: Vishay
R76 R126 R127 R478 = Res_0: Desc: RES 0.0 OHM 1/10W 0402 SMD; Part Num: ERJ-2GE0R00X; Vendor: Panasonic; ccc: RES 0.0 OHM 1/10W 0402 SMD
R78 = Res_0: Desc: RES 150K OHM 1/16W 5% 0402 SMD; Part Num: MCR01MZPJ154; Vendor: Rohm
R138 R332 R488 = R_0: Desc: RES 0.0 OHM 1/10W 0603 SMD; Mfr: Generic; Part Num: ERJ-3GEY0R00V; Vendor: Panasonic
R272 R277 = Res_0: Desc: RES 100K OHM 1/16W 5% 0402 SMD; Part Num: CRCW0402100KJNED; Vendor: Vishay
U23 = 32.768_OSC: Desc: OSCILLATOR 32.768KHZ 1.8V SMD; Part Num: 7XZ3270008; Vendor: TXC
U99 = AW-NH387: Desc: MODULE WIFI 8787 2.4G; Vendor: AzureWave
C115 = CAP_NP_2: Desc: CAP CER 10UF 10V 10% X5R 0603; Part Num: C1608X5R1A106K080AC; Vendor: TDK
C119 C125 C127 = CAP_NP_2: Desc: CAP CER 10UF 6.3V 20% X5R 0402; Part Num: C1005X5R0J106M050BC; Vendor: TDK
C128-C131 = CAP_NP_0: Desc: CAP 100pF 10% 0402 25V X7R; Part Num: ECJ-0EB1E101K; Vendor: Panasonic
C337 C384 C385 C390 = CAP_NP_0: Desc: CAP CER 33PF 50V 5% NP0 0402; Part Num: C1005C0G1H330J050BA; Vendor: TDK
FB8-FB11 = FERRITE_BEAD_0: Desc: FERRITE CHIP 47 OHM 300MA 0603; Part Num: BLM18BA470SN1; Vendor: Murata
J27 = CON2: Desc: CONN HEADER PH SIDE 2POS 2MM SMD; Part Num: S2B-PH-SM4-TB(LF)(SN); Vendor: JST
J51 J52 = CON2: Desc: CONN HEADER ACH SIDE 2POS 1.2MM; Part Num: BM02B-ACHSS-GAN-TF(LF)(SN); Vendor: JST
R74 R391 = Res_0: Desc: RES 1.5K OHM 1/10W 5% 0402 SMD; Part Num: ERJ-2GEJ152X; Vendor: Panasonic; ccc: RES 0.0 OHM 1/10W 0402 SMD
U8 = AUD155_V3B: Desc: IC CODEC HP STEREO HP SPKR DRVR; Part Num: 88CE156A0NAJ2C000; Vendor: Marvell
J48 = CONN_FLEX_51: Desc: CONN FPC 51POS 0.3MM SMD; Part Num: FH35-51S-0.3SHW(50); Vendor: HIrose
R145 = Res_0: Desc: RES 3.3K OHM 1/10W 5% 0402 SMD; Mfr: Generic; Part Num: ERJ-2GEJ332X; Vendor: Panasonic
RP13-RP19 = RPACK4: Desc: RES ARRAY 51 OHM 5% 4 RES SMD; Part Num: EXB-28V510JX; Vendor: Panasonic; fff: RES ARRAY 150 OHM 5% 4 RES SMD
TP6-TP11 = T_POINT: Desc: SMT Test Point; Part Num: NA; Vendor: Test
C103 = CAP_NP_0: CAP CER 0.10uF 6.3V X5R 0201; Desc: CAP CER .10UF 10V X7R 0402; Manufacturer: Taiyo Yuden; Manufacturer_PN: JMK063BJ104KP-F; OPTION: LIPO; Part Num: C1005X7R1A104K; Vendor: TDK
C351 C377 C378 = CAP_NP_0: Desc: CAP CER 1UF 10V 10% X5R 0402; OPTION: LIPO; Part Num: C1005X5R1A105K050BB; Vendor: TDK; ccc: CAP CER 1UF 10V 10% X5R 0402
C352 C353 C380 = CAP_NP_0: Desc: CAP CER 10UF 10V 10% X5R 0603; OPTION: LIPO; Part Num: C1608X5R1A106K080AC; Vendor: TDK
C354 C361 = CAP_NP_0: Desc: CAP CER 560PF 25V 5% NP0 0402; OPTION: LIPO; Part Num: C1005C0G1E561J; Vendor: TDK
C357 C358 C379 = CAP_NP_0: Desc: CAP CER 4.7UF 10V 10% X5R 0603; OPTION: LIPO; Part Num: LMK107BJ475KA-T; Vendor: Taiyo
C360 = CAP_NP_0: Desc: CAP CER 3300PF 10V 5% SL 0402; OPTION: LIPO; Part Num: C1005SL1A332J; Vendor: TDK
D28 = DIODE_SCHOTTKY21: DIODE SCHOTTKY 1A 40V SMA; Desc: DIODE SCHOTTKY 1A 40V SMA; Manufacturer: Fairchild; Vendor: Fairchild
D33 = Diodesot23: Desc: DIODE SCHOTTKY 30V 0.2A SOT23-3; Vendor: Fairchild
J50 = CON3: Desc: CONN HEADER PH SIDE 3POS 2MM SMD; Part Num: S3B-PH-SM4-TB(LF)(SN); Vendor: JST
L36 = IND_SMALL: Desc: INDUCTOR POWER 2.7UH 1.5A 0302; OPTION: LIPO; Part Num: SDR0302-2R7ML; Vendor: Bourns
NTC1 = Thermistor: Desc: THERMISTOR NTC 10K OHM 5% 0402; Part Num: ERT-J0EM103J; Vendor: Panasonic
R171 = R_0: RES 10.0K OHM 1/10W 1% 0402 SMD; Desc: RES 10K OHM 1/10W 5% 0402 SMD; Manufacturer: Panasonic - ECG; Manufacturer_PN: ERJ-2RKF1002X; OPTION: LIPO; Part Num: ERJ-2GEJ103X; Vendor: Panasonic
R420 = Res_0: Desc: RES 47K OHM 1/10W 1% 0402 SMD; OPTION: LIPO; Part Num: ERJ-2RKF4702X; Vendor: Panasonic
R421 R423 R438 R549-R551 R560-R563 = Res_0: Desc: RES 10K OHM 1/10W 5% 0402 SMD; OPTION: LIPO; Part Num: ERJ-2GEJ103X; Vendor: Panasonic
R422 = Res_0: Desc: RES 30.1K OHM 1/10W 1% 0402 SMD; OPTION: LIPO; Part Num: ERJ-2RKF3012X; Vendor: Panasonic
R480 R483 = Res_0: Desc: RES 1K OHM 1/10W 1% 0402 SMD; OPTION: LIPO; Part Num: ERJ-2RKF1001X; Vendor: Panasonic
R482 = Res_0: Desc: RES 1M OHM 1/10W 1% 0402 SMD; OPTION: LIPO; Part Num: ERJ-2RKF1004X; Vendor: Panasonic; d: RES 1K OHM 1/10W 1% 0402 SMD
R487 = Res_0: Desc: RES 1K OHM 1/10W 1% 0402 SMD; OPTION: LIPO; Part Num: ERJ-2RKF1001X; Vendor: Panasonic; d: RES 1K OHM 1/10W 1% 0402 SMD
R489 R514-R517 R552 R553 R564 R565 = Res_0: Desc: RES 0.0 OHM 1/10W 0402 SMD; Part Num: ERJ-2GE0R00X; Vendor: Panasonic
R531 = Res_0: Desc: RES 510K OHM 1/10W 5% 0402 SMD; Mfr: Generic; Part Num: ERJ-2GEJ514X; Vendor: Panasonic
U146 = MAX17058TDFN
U150 = MAX17112
U169 = RT9525

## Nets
FLX1_3VENH/5VENL: U1.E13(MFP_26_(FN0)) ; also on sheet 15
FLX2_3VENH/5VENL: U1.A15(MFP_22_(FN5)) ; also on sheet 16
GND: C7.2 C8.2 C9.2 C12.2 C13.2 C14.2 C23.2 C24.2 C25.2 C26.2 C27.2 C29.2 C30.1 C31.2 C32.1 C33.2 C35.2 C36.2 C37.2 C38.2 C41.2 C42.2 C43.2 C44.2 C45.2 C47.2 C48.2 C51.1 C52.2 C53.2 C54.2 C55.2 C56.2 C57.2 C58.2 C59.2 C60.2 C66.1 C68.2 C69.2 C70.2 C71.2 C72.2 C73.2 C74.2 C77.2 C78.2 C80.2 C81.2 C82.2 C85.2 C86.2 C87.2 C88.2 C89.2 C90.2 C91.2 C92.2 C97.2 C101.2 C102.2 C103.2 C114.1 C115.2 C116.1 C117.1 C118.1 C119.2 C120.1 C121.1 C122.1 C124.1 C125.2 C126.1 C127.2 C128.2 C129.2 C130.2 C131.2 C133.2 C135.2 C136.2 C137.2 C138.2 C139.2 C140.2 C141.2 C143.2 C144.2 C145.2 C172.2 C173.2 C177.2 C197.2 C351.2 C352.2 C353.2 C354.2 C357.2 C358.2 C360.2 C361.2 C374.2 C375.2 C377.2 C378.2 C379.2 C380.2 C383.2 C384.1 C385.1 J6.2(GND1) J6.3(GND2) J30.6(VSS) J30.9(MTG9) J30.10(MTG10) J30.11(MTG11) J30.12(MTG12) J48.5 J48.6 J48.13 J48.20 J48.27 J48.34 J48.51 J48.M1 J48.M2 J50.2 L2.1 L3.1 NTC1.1(A) Q3.2(E) Q3.3(C) Q5.S Q16.S Q93.S Q114.S Q122.S Q123.S R4.2 R6.2 R12.1 R15.1 R16.1 R40.2 R41.2 R42.2(B) R46.1 R54.1 R69.1 R123.2 R124.2 R125.2 R145.2 R277.1 R391.2 R421.2 R438.2 R479.1 R480.2 R482.2 R483.2 R526.2 R528.2 R531.1 R549.2 R550.2 R561.2 R563.2 U1.C6(VSS_1) U1.C10(VSS_2) U1.C16(VSS_52) U1.F7(VSS_53) U1.F8(VSS_54) U1.F9(VSS_55) U1.F10(VSS_56) U1.F11(VSS_57) U1.F12(VSS_58) U1.G6(VSS_59) U1.G7(VSS_3) U1.G8(VSS_4) U1.G9(VSS_5) U1.G10(VSS_6) U1.G11(VSS_7) U1.G12(VSS_8) U1.G13(VSS_60) U1.H6(VSS_61) U1.H7(VSS_9) U1.H8(VSS_10) U1.H9(VSS_11) U1.H10(VSS_12) U1.H11(VSS_13) U1.H12(VSS_14) U1.H13(VSS_62) U1.J6(VSS_63) U1.J7(VSS_15) U1.J8(VSS_16) U1.J9(VSS_17) U1.J10(VSS_18) U1.J11(VSS_19) U1.J12(VSS_20) U1.J13(VSS_64) U1.K6(VSS_65) U1.K7(VSS_21) U1.K8(VSS_22) U1.K9(VSS_23) U1.K10(VSS_24) U1.K11(VSS_25) U1.K12(VSS_26) U1.K13(VSS_66) U1.L6(VSS_67) U1.L7(VSS_27) U1.L8(VSS_28) U1.L9(VSS_29) U1.L10(VSS_30) U1.L11(VSS_31) U1.L12(VSS_32) U1.L13(VSS_68) U1.L18(VSS_33) U1.M6(VSS_69) U1.M7(VSS_34) U1.M8(VSS_35) U1.M9(VSS_36) U1.M10(VSS_37) U1.M11(VSS_38) U1.M12(VSS_39) U1.M13(VSS_70) U1.N7(VSS_40) U1.N8(VSS_41) U1.N11(VSS_42) U1.N12(VSS_43) U1.N14(VSS_74) U1.N16(VSS_80) U1.P5(VSS_75) U1.P7(VSS_44) U1.P12(VSS_45) U1.P14(VSS_76) U1.P15(VSS_82) U1.T2(VSS_46) U1.T4(VSS_47) U1.T8(VSS_48) U1.T11(VSS_49) U1.T14(VSS_50) U1.T16(VSS_77) U1.U6(VSS_51) U1.V16(VSS_81) U2.A9(VSS_1) U2.B1(VSSQ_1) U2.B3(VSS_2) U2.B9(VSSQ_2) U2.D1(VSSQ_3) U2.D8(VSSQ_4) U2.E1(VSS_3) U2.E2(VSSQ_5) U2.E8(VSSQ_6) U2.F9(VSSQ_7) U2.G1(VSSQ_8) U2.G8(VSS_4) U2.G9(VSSQ_9) U2.J2(VSS_5) U2.J8(VSS_6) U2.M1(VSS_7) U2.M9(VSS_8) U2.P1(VSS_9) U2.P9(VSS_10) U2.T1(VSS_11) U2.T9(VSS_12) U8.17(DGND) U8.33(GND_PAD) U23.2(GND) U99.1(Gnd1) U99.3(Gnd2) U99.4(Gnd3) U99.12(Gnd4) U99.24(Gnd5) U99.36(Gnd6) U99.46(Gnd12) U99.47(Gnd13) U99.48(Gnd14) U99.49(Gnd15) U99.51(Gnd16) U99.53(Gnd31) U99.54(Gnd54) U99.55(Gnd55) U99.56(Gnd56) U99.57(Gnd57) U99.58(Gnd58) U99.59(Gnd59) U99.60(Gnd60) U99.61(Gnd61) U99.62(Gnd62) U99.63(Gnd63) U99.64(Gnd64) U99.65(Gnd65) U99.68(Gnd68) U99.75(Gnd75) U99.79(Gnd79) U99.80(Gnd80) U99.82(Gnd82) U99.83(Gnd83) U126.4(VSS) U126.9(TPAD) U146.1(CTG) U146.4(GND) U146.6(QSTRT) U146.PAD U150.4(GND) U150.5(GND) U150.EP(PAD) U169.8(GND) U169.EP(GND) ; also on sheet 10 11 12 13 14 15 16
V1P2_MAU: C118.2 C119.1 U8.16(DCVDD)
V1P5_DDR: C85.1 C86.1 C87.1 C88.1 C89.1 C90.1 C91.1 C92.1 C101.1 C172.1 Q7.S R44.2 R45.2 U2.A1(VDDQ_1) U2.A8(VDDQ_2) U2.B2(VDD_1) U2.C1(VDDQ_3) U2.C9(VDDQ_4) U2.D2(VDDQ_5) U2.D9(VDD_2) U2.E9(VDDQ_6) U2.F1(VDDQ_7) U2.G7(VDD_3) U2.H2(VDDQ_8) U2.H9(VDDQ_9) U2.K2(VDD_4) U2.K8(VDD_5) U2.N1(VDD_6) U2.N9(VDD_7) U2.R1(VDD_8) U2.R9(VDD_9) ; also on sheet 10
V1P5_DDR_A: C8.1 C35.1 C36.1 C37.1 C38.1 C41.1 C42.1 C43.1 C44.1 C45.1 C47.1 C48.1 C51.2 C173.1 Q1.G Q7.D R7.1 R11.1 R13.2 R14.1 R281.2 U1.P9(VDD_M_1) U1.R2(VDD_M_2) U1.R4(VDD_M_3) U1.T7(VDD_M_4) U1.T10(VDD_M_5) U1.T13(VDD_M_6) U1.U3(VDD_M_7) U1.U5(VDD_M_8)
V1P8: C144.1 C145.1 C177.1 C197.1 FB46.1 Q19.S Q113.S R68.1 R126.2 U99.37(VDD18_X3) ; also on sheet 10
V1P8_MAU: C124.2 C125.1 FB6.2 U8.24(HPVDD)
V1P8_OSC: C23.1 C24.1 C80.1 FB15.2 U1.P16(AVDD_OSC)
V1P8A_WIFI: C138.1 C139.1 FB46.2 U99.41(VDD1.8A)
V3P3: C12.1 C13.1 C14.1 C25.1 C26.1 C27.1 C29.1 C30.2 C77.1 C102.1 C374.1 C375.1 C386.2 C387.2 C388.2 C389.2 J30.4(VDD) Q4.S Q112.S R1.1 R38.1 R50.1 R52.1 R73.2 R82.2 R83.2 R84.2 R101.2 R138.1 R171.1 R316.2 R317.2 R477.2 U1.C4(VDD_IO2_1) U1.C7(VDD_IO2_2) U1.C9(VDD_IO2_3) U1.E5(VDD_IO4_1) U1.E14(VDD_IO0_2) U1.F5(VDD_IO4_2) U1.F14(VDD_IO0_1) U1.J5(VDD_IO3_1) U1.J14(VDD_IO1_2) U1.K5(VDD_IO3_2) U1.K14(VDD_IO1_1) U99.35(VIO_X2) U99.38(VIO_X1) U126.8(VCC) ; also on sheet 10 11 13 14 15 16
V3P3_MAU: C126.2 C127.1 FB5.1 Q114.G R332.2 R528.1 U8.18(DBVDD)
V3P3_MAUAVDD: C114.2 FB5.2 U8.3(AVDD_BYP)
V3P3_USB_A: C31.1 C32.2 C33.1 C78.1 Q4.D U1.M16(AVDD_USB_UHC) U1.N15(AVDD_USB_OTG) ; also on sheet 11
V3P3_WIFI: C133.1 C143.1 FB45.1 R78.2 R129.1 R138.2 R272.2 U99.19(VBAT)
V3P3A_WIFI: C136.1 C137.1 FB45.2 U99.9(3.3V_PA)
V5P0_MAU_PA: C115.1 C117.2 FB4.2 U8.26(SPKVDD2) U8.29(SPKVDD1)
VIN: C379.1 R423.1 R551.1 R560.1 R562.1 U169.13(VIN) ; also on sheet 12
VIN_H: Q93.G Q117.G Q122.D R423.2 R438.1 R531.2
2G_WLAN_BT: C142.2 C334.1 L3.2 U99.2(2G_WLAN/BT_RF)
2G_WLAN_BT_ANT: A2.1(Feed1) A2.2(Feed2) C142.1 L2.2
AP_AP2WLAN_WAKEUP: C141.1 R277.2 U99.10(WLAN-MAC_Wake/GPIO4) ; also on sheet 11
AP_UART2_CBUS0: U1.C14(MFP_24_(FN5)) ; also on sheet 14
AP_UART2_RX: J48.44 ; also on sheet 11 14
AP_UART2_TX: J48.45 ; also on sheet 11 14
ASPEN_DDR_RST#: Q1.S R7.2 R336.2 U1.V14(VSS_(M_RST#_OUTPUT))
AUDIO_ADCDAT: U8.13(SDOUT) ; also on sheet 11
AUDIO_BCLK: U8.12(BCLK) ; also on sheet 11
AUDIO_DACDAT: U8.14(SDIN) ; also on sheet 11
AUDIO_LRCK: U8.15(LRCK) ; also on sheet 11
AUDIO_MCLK: U8.11(MCLK) ; also on sheet 11
BSTEN_H/CHRGEN_L: C360.1 D33.3(A) Q93.D U150.9(\~{SHD}N) ; also on sheet 12
CE156ON_L: Q112.G Q113.G R526.1 ; also on sheet 11
CHGR_EN0: D33.1(C1) Q123.D R551.2 U169.4(~{EN})
CHGSB: U1.F17(MFP_1_(MMC3_DAT6)_(FN6)) U169.9(~{CHG})
DDR_BA0: U1.T9(M_BA0) U2.M2(BA0)
DDR_BA1: U1.R9(M_BA1) U2.N8(BA1)
DDR_BA2: U1.P10(M_BA2) U2.M3(BA2)
DDR_CALPAD: R6.1 U1.N4(CALPAD)
DDR_CAS#: U1.V9(M_CAS#) U2.K3(CAS_N)
DDR_CKE0: R41.1 U1.R7(M_CKE0) U2.K9(CKE)
DDR_CLK: R10.2 U1.V6(M_CLK0) U2.J7(CK_P)
DDR_CLK#: R9.2 U1.V7(M_CLK0#) U2.K7(CK_N)
DDR_CS0#: U1.R8(M_CS0#) U2.L2(CS_N)
DDR_DQ0: U1.P2(MDQ0) U2.E3(DQ0)
DDR_DQ1: U1.P3(MDQ1) U2.F7(DQ1)
DDR_DQ2: U1.P4(MDQ2) U2.F2(DQ2)
DDR_DQ3: U1.R3(MDQ3) U2.F8(DQ3)
DDR_DQ4: U1.T3(MDQ4) U2.H3(DQ4)
DDR_DQ5: U1.U1(MDQ5) U2.H8(DQ5)
DDR_DQ6: U1.U2(MDQ6) U2.G2(DQ6)
DDR_DQ7: U1.V1(MDQ7) U2.H7(DQ7)
DDR_DQ8: U1.V3(MDQ8) U2.D7(DQ8)
DDR_DQ9: U1.U4(MDQ9) U2.C3(DQ9)
DDR_DQ10: U1.R5(MDQ10) U2.C8(DQ10)
DDR_DQ11: U1.T5(MDQ11) U2.C2(DQ11)
DDR_DQ12: U1.P6(MDQ12) U2.A7(DQ12)
DDR_DQ13: U1.R6(MDQ13) U2.A2(DQ13)
DDR_DQ14: U1.T6(MDQ14) U2.B8(DQ14)
DDR_DQ15: U1.U7(MDQ15) U2.A3(DQ15)
DDR_DQM0: U1.P1(M_DQM0) U2.E7(LDM)
DDR_DQM1: U1.V2(M_DQM1) U2.D3(UDM)
DDR_DQS0: R12.2 U1.T1(M_DQS0) U2.F3(LDQS_P)
DDR_DQS0#: R11.2 U1.R1(M_DQS0#) U2.G3(LDQS_N)
DDR_DQS1: R15.2 U1.V5(M_DQS1) U2.C7(UDQS_P)
DDR_DQS1#: R14.2 U1.V4(M_DQS1#) U2.B7(UDQS_N)
DDR_MA0: U1.R10(MA0) U2.N3(CA0)
DDR_MA1: U1.U10(MA1) U2.P7(CA1)
DDR_MA2: U1.V10(MA2) U2.P3(CA2)
DDR_MA3: U1.R11(MA3) U2.N2(CA3)
DDR_MA4: U1.U11(MA4) U2.P8(CA4)
DDR_MA5: U1.V11(MA5) U2.P2(CA5)
DDR_MA6: U1.V12(MA6) U2.R8(CA6)
DDR_MA7: U1.U12(MA7) U2.R2(CA7)
DDR_MA8: U1.T12(MA8) U2.T8(CA8)
DDR_MA9: U1.R12(MA9) U2.R3(CA9)
DDR_MA10: U1.V13(MA10) U2.L7(CA10)
DDR_MA11: U1.U13(MA11) U2.R7(CA11)
DDR_MA12: U1.R13(MA12) U2.N7(CA12)
DDR_MA13: U1.P13(MA13) U2.T3(CA13)
DDR_MA14: U1.R14(MA14) U2.T7(CA14)
DDR_ODT0: U1.U8(M_ODT0) U2.K1(ODT)
DDR_RAS#: U1.V8(M_RAS#) U2.J3(RAS_N)
DDR_RST#: Q1.D R44.1 R336.1 U2.T2(RESET_N)
DDR_VREF_ASPEN: C9.1 R13.1 R16.2 U1.N1(VREF)
DDR_WE#: U1.U9(M_WE#) U2.L3(WE_N)
EXP_OC_L: U1.D16(MFP_10_(FN5)) ; also on sheet 13
FLX1_OC_L: U1.D15(MFP_11_(FN5)) ; also on sheet 15
FLX2_OC_L: U1.C18(MFP_12_(FN5)) ; also on sheet 16
GG_SCL: R515.1 R516.1 U146.7(SCL)
GG_SDA: R514.1 R517.1 U146.8(SDA)
HIB_EN: R489.2 ; also on sheet 12
HSI_0: R124.1 U99.45(HSI0)
HSI_1: R125.1 U99.43(HSI1)
HSI_2: R123.1 U99.33(ECS#/HSI2)
LCD_DD0: RP16.7(R7) U1.E10(MFP_60_(LCD_DD0)_(FN1))
LCD_DD1: RP17.1(R1) U1.D10(MFP_61_(LCD_DD1)_(FN1))
LCD_DD2: RP18.7(R7) U1.B10(MFP_62_(LCD_DD2)_(FN1))
LCD_DD3: RP13.1(R1) U1.A10(MFP_63_(LCD_DD3)_(FN1))
LCD_DD4: RP13.3(R3) U1.A9(MFP_64_(LCD_DD4)_(FN1))
LCD_DD5: RP18.5(R5) U1.B9(MFP_65_(LCD_DD5)_(FN1))
LCD_DD6: RP16.5(R5) U1.D9(MFP_66_(LCD_DD6)_(FN1))
LCD_DD7: RP17.3(R3) U1.E9(MFP_67_(LCD_DD7)_(FN1))
LCD_DD8: RP16.3(R3) U1.A8(MFP_68_(LCD_DD8)_(FN1))
LCD_DD9: RP17.7(R7) U1.B8(MFP_69_(LCD_DD9)_(FN1))
LCD_DD10: RP17.5(R5) U1.C8(MFP_70_(LCD_DD10)_(FN1))
LCD_DD11: RP16.1(R1) U1.D8(MFP_71_(LCD_DD11)_(FN1))
LCD_DD12: RP15.1(R1) U1.A7(MFP_72_(LCD_DD12)_(FN1))
LCD_DD13: RP15.3(R3) U1.B7(MFP_73_(LCD_DD13)_(FN1))
LCD_DD14: RP15.5(R5) U1.D7(MFP_74_(LCD_DD14)_(FN1))
LCD_DD15: RP14.3(R3) U1.E7(MFP_75_(LCD_DD15)_(FN1))
LCD_DD16: RP14.7(R7) U1.A6(MFP_76_(LCD_DD16)_(FN1))
LCD_DD17: RP14.5(R5) U1.B6(MFP_77_(LCD_DD17)_(FN1))
LCD_DD18: RP14.1(R1) U1.D6(MFP78_(LCD_DD18)_(FN1))
LCD_DD19: RP19.7(R7) U1.E6(MFP79_(LCD_DD19)_(FN1))
LCD_DD20: RP19.3(R3) U1.A5(MFP80_(LCD_DD20)_(FN1))
LCD_DD21: RP19.1(R1) U1.B5(MFP81_(LCD_DD21)_(FN1))
LCD_DD22: RP19.5(R5) U1.C5(MFP82_(LCD_DD22)_(FN1))
LCD_DD23: RP13.5(R5) RP15.7(R7) U1.D5(MFP83_(LCD_DD23)_(FN1))
LCD_DENA_SMPNVS: R520.2 U1.A11(MFP_59_(LCD_DENA_BIAS)_(FN1))
LCD_LCLK_A0: RP18.1(R1) U1.C11(MFP_57_(LCD_LCLK_A0)_(FN1))
LCD_PCLK_WRB: RP13.7(R7) U1.B11(MFP_58_(LCD_PCLK_WR)_(FN1))
LCD_PWM: J48.4 R145.1 U1.A4(MFP84_(PWM1_BL_CONTROL)_(FN4))
LCD_RST2: R333.2 U1.B4(MFP85_(GPO_BL_PWREN)_(FN0))
LCD_VFCLK_RDB: RP18.3(R3) U1.D11(MFP_56_(LCD_FCLK_RD)_(FN1))
LCDB_DD0: J48.7 RP16.8(R72)
LCDB_DD1: J48.8 RP17.2(R12)
LCDB_DD2: J48.9 RP18.8(R72)
LCDB_DD3: J48.10 RP13.2(R12)
LCDB_DD4: J48.11 RP13.4(R32)
LCDB_DD5: J48.12 RP18.6(R52)
LCDB_DD6: J48.14 RP16.6(R52)
LCDB_DD7: J48.15 RP17.4(R32)
LCDB_DD8: J48.16 RP16.4(R32)
LCDB_DD9: J48.17 RP17.8(R72)
LCDB_DD10: J48.18 RP17.6(R52)
LCDB_DD11: J48.19 RP16.2(R12)
LCDB_DD12: J48.21 RP15.2(R12)
LCDB_DD13: J48.22 RP15.4(R32)
LCDB_DD14: J48.23 RP15.6(R52)
LCDB_DD15: J48.24 RP14.4(R32)
LCDB_DD16_SMPNCS1: J48.25 RP14.8(R72)
LCDB_DD17_SMPNCS0: J48.26 RP14.6(R52)
LCDB_DD18_SPICS1_SMPNCS0: J48.31 RP14.2(R12)
LCDB_DD19_SPICS0: J48.39 RP19.8(R72) TP10.1(TP)
LCDB_DD20_SPIDIN: J48.37 RP19.4(R32) TP8.1(TP)
LCDB_DD21_SPIDOUT: J48.36 RP19.2(R12) TP7.1(TP)
LCDB_DD22_SPIDCLK: J48.38 RP19.6(R52) TP9.1(TP)
LCDB_DD23_BIAS_RST: J48.33 RP15.8(R72)
LCDB_DD23_DENA_BIAS: RP13.6(R52) TP6.1(TP)
LCDB_DENA_SMPNVS: J48.32 R520.1
LCDB_GPIO_RST: J48.35 R333.1 TP11.1(TP)
LCDB_LCLK_A0: J48.30 RP18.2(R12)
LCDB_PCLK_WRB: J48.29 RP13.8(R72)
LCDB_VFCLK_RDB: J48.28 RP18.4(R32)
LOW_BATT: R171.2 U146.5(ALRT) ; also on sheet 11 12
MFP90: J48.47 ; also on sheet 11 13
MFP91: J48.48 ; also on sheet 11 13
MFP92: J48.49 ; also on sheet 11 13
MFP93: J48.50 ; also on sheet 11 13
MFP_I2C_INTR: U1.B17(MFP_15_(FN5)) ; also on sheet 13
MFP_SCL: J48.43 R516.2 U8.19(SCLK) ; also on sheet 11 13
MFP_SDA: J48.42 R517.2 U8.20(SDAT) ; also on sheet 11 13
MIC1N: C336.1 C390.2 U8.5(MIC1N/LINEIN_L)
MIC1N_C: C336.2 C337.2 C385.2 J27.2 R391.1
MIC1P: C335.1 C390.1 U8.6(MIC1P)
MIC1P_C: C335.2 C337.1 C384.2 J27.1 R74.1
MICBIAS_M: C383.1 R74.2 U8.4(MICBIAS)
MMC3_CLK: J30.5(CLK) U1.E12(MFP36_(MMC3_CLK)_(FN6))
MMC3_CMD: J30.3(CMD) R83.1 U1.A12(MFP35_(MMC3_CMD)_(FN6))
MMC3_D0: J30.7(DAT0) R73.1 U1.E15(MFP_7_(MMC3_DAT0)_(FN6))
MMC3_D1: J30.8(DAT1) R82.1 U1.E16(MFP_6_(MMC3_DAT1)_(FN6))
MMC3_D2: J30.1(DAT2) R101.1 U1.E17(MFP_5_(MMC3_DAT2)_(FN6))
MMC3_D3: J30.2(CD/DAT3) R84.1 U1.E18(MFP_4_(MMC3_DAT3)_(FN6))
OTG_PWRH: Q122.G R549.1 ; also on sheet 11
PGB: U1.F18(MFP_0_(MMC3_DAT7)_(FN6)) U169.7(~{PG})
PWR_SCL: R515.2 ; also on sheet 10 11
PWR_SDA: R514.2 ; also on sheet 10 11
RF_TEST: C334.2 J6.1(CENTER)
RT9525_EN1: R560.2 R561.1 R564.1 U169.5(EN1)
RT9525_EN2: R562.2 R563.1 R565.1 U169.6(EN2)
RT_EN0: R553.2 U1.C13(MFP_27_(FN5))
RT_EN1: R564.2 U1.A18(MFP_16_(GPO_LR)(FN0))
RT_EN2: R565.2 U1.B16(MFP_18_(GPO_UD)(FN0))
RT_SYSOFF: R483.1 R489.1 U169.15(SYSOFF)
SLEEP_CLK: R127.1 U99.22(Sleep_CLK)
SLP_CLK_OUT: R127.2 U23.3(OUT)
SPI_CLK: U126.6(C) ; also on sheet 11
SPI_FRM: R465.1 ; also on sheet 11
SPI_NOR_ON: R464.1 ; also on sheet 11
SPI_RXD: U126.2(Q) ; also on sheet 11
SPI_TXD: U126.5(D) ; also on sheet 11
SPI_WP#: R52.2 R479.2 U126.3(~{W})
SPK_OUT_L: FB9.1 U8.30(SPK_LP)
SPK_OUT_LN: FB8.1 U8.28(SPK_LN)
SPK_OUT_R: FB11.1 U8.25(SPK_RP)
SPK_OUT_RN: FB10.1 U8.27(SPK_RN)
TOUCH_INTR: J48.41 U1.B18(MPF_14_(FN5))
TOUCH_RST: J48.46 U1.D17(MFP_9)
UART2_CBUS0: R552.2 ; also on sheet 14
USB_C_VBUS: U1.P18(AVDD5_USB) ; also on sheet 11
V_MBAT: C103.1 C357.1 C358.1 C377.1 J50.1 L36.1 U146.2(CELL) U146.3(VDD) U150.8(IN) U169.2(BAT) U169.3(BAT)
VCORE: C52.1 C53.1 C54.1 C55.1 C56.1 C57.1 C58.1 C59.1 C60.1 C66.2 C68.1 C69.1 C70.1 C71.1 C72.1 C73.1 C74.1 C97.1 C388.1 C389.1 Q5.G R40.1 U1.E8(VDD_CORE_11) U1.E11(VDD_CORE_12) U1.G5(VDD_CORE_3) U1.G14(VDD_CORE_4) U1.H5(VDD_CORE_2) U1.H14(VDD_CORE_1) U1.L5(VDD_CORE_5) U1.L14(VDD_CORE_6) U1.M5(VDD_CORE_7) U1.M14(VDD_CORE_8) U1.P8(VDD_CORE_9) U1.P11(VDD_CORE_10) U1.T17(RFU_(VDD_CORE)) ; also on sheet 10
VCOREON: Q4.G Q5.D Q7.G Q16.G Q19.G R38.2
VLCD: J48.1 R317.1
VLCD_BL: J48.2 J48.3 R316.1 R440.1
VREF_DDR: C81.1 C82.1 R45.1 R46.2 U2.H1(VREF_DQ) U2.M8(VREF_CA)
VSYS: C386.1 C387.1 R440.2 ; also on sheet 10 12 13 15 16
VSYS_BOOST: C352.1 C353.1 D28.1(K) Q117.S R422.1
VSYS_HIB: Q111.S R488.2 R527.1 ; also on sheet 10 12
VSYS_IN: Q117.D ; also on sheet 12
VTOUCH: J48.40 R477.1
WLAN_IRQ: R129.2 U99.52(GPIO16/WLAN_host_wakeup) ; also on sheet 11
WLAN_LED: R478.1 U99.11(WLAN_LED/GPIO1)
WLAN_PDn: R272.1 U99.18(PD#) ; also on sheet 11
WLAN_RESETn: R76.1 U99.39(RESET#) ; also on sheet 11
WLAN_SD0: U99.26(SD_D0/SPI_CS#) ; also on sheet 11
WLAN_SD1: U99.13(SD_D1/SPI_DO#) ; also on sheet 11
WLAN_SD2: U99.25(SD_D2/SPI_SInt#) ; also on sheet 11
WLAN_SD3: U99.14(SD_D3) ; also on sheet 11
WLAN_SDCLK: U99.27(SD_CLK/SPI_CLK) ; also on sheet 11
WLAN_SDCMD: U99.29(SD_CMD/SPI_DI) ; also on sheet 11
N32501699: C7.1 R9.1 R10.1
N40044826: R1.2 R4.1 U1.N5(VSS_(SEC_CS_EN))
N40391928: R68.2 R69.2 U1.T15(RFU_(AVDDT_PCIE)) U1.U16(RFU_(AVDD_PCIE))
N40401834: Q3.1(B) U1.R16(RFU_(RT_SEN))
N41867809: C135.1 U99.40(1.2V_EXT)
N41867996: C140.1 R126.1 U23.4(VDD)
N41869043: R76.2 R78.1
N41905335: FB15.1 Q19.D
N42190736: R42.1(A) U2.L8(ZQ)
N42554742: C128.1 FB9.2 J51.2
N42554913: C123.2 U8.23(FLYP)
N42554915: C123.1 U8.21(FLYN)
N42555160: C116.2 U8.22(VSS_HP_BYP)
N42555188: C121.2 U8.2(VREF)
N42555198: C120.2 U8.7(VCM_BYP)
N42555204: C122.2 U8.8(VOCCP)
N42555241: C129.1 FB8.2 J51.1
N42555698: C130.1 FB11.2 J52.2
N42555707: C131.1 FB10.2 J52.1
N42564866: R54.2 R464.2 R465.2 U126.1(~{S})
N42564868: R50.2 U126.7(~{HOLD})
N42945467: C351.1 U150.3(VL)
N42945743: D28.2(A) L36.2 U150.6(LX1) U150.7(LX2)
N42945993: R421.1 R422.2 U150.2(FB)
N42946021: R420.1 U150.1(COMP)
N42946045: C354.1 R420.2
N42946061: C361.1 U150.10(SS)
N43131362: R478.2 U99.44(BT_LED/GPIO17)
N43158087: R480.1 U169.16(ISETA)
N43158213: C380.1 R488.1 U169.10(SYS) U169.11(SYS)
N43158323: C378.1 U169.14(TIMER)
N43158664: R482.1 R487.1 U169.1(TS)
N43166289: NTC1.2(B) R487.2
N43468083: Q16.D R281.1
N43488330: FB4.1 Q111.D
N43488337: Q112.D R332.1
N43488344: FB6.1 Q113.D
N43489932: Q111.G Q114.D R527.2
N43551507: Q123.G R550.1 R552.1 R553.1

Not connected (* = marked no-connect by the designer): A2 3(TIP)*; D33 2(NC)*; J50 3*; U1 A17(MFP_17_(FN5))* B15(MFP_21_(FN5))* C12(MFP34_(GPO_PWREN)_(FN0))* C17(MFP_13_(FN5))* D18(MFP_8)* F15(MFP_3_(MMC3_DAT4)_(FN6))* F16(MFP_2_(MMC3_DAT5)_(FN6))* N9(VSS_(M_CKE1))* N10(VSS_(M_CS1#))* R15(RFU) U14(VSS_(M_ODT1))* U15(RFU_(PCIETX)) U17(RFU_(PCIERX)) U18(RFU_(PCIECLK)) V15(RFU_(PCIETX#)) V17(RFU_(PCIERX#)) V18(RFU_(PCIECLK#)); U2 J1(NC_1)* J9(NC_2)* L1(NC_3)* L9(NC_4)* M7(NC_5)*; U8 1(HPS)* 9(MIC2P)* 10(MIC2N/LINEIN_R)* 31(HP_R)* 32(HP_L)*; U23 1(OE)*; U99 5(I2S_DO)* 6(Uart_DSR/GPIO3)* 7(EX_OSC_CTL/GPIO0)* 8(FM_RX)* 15(FM_TX)* 16(Uart_DTR/GPIO5)* 17(Uart_SIN/GPIO7)* 20(I2S_DIN)* 21(Uart_CTS#/GPIO8)* 23(I2S_BCLK)* 28(PCM_DO/GPIO12)* 30(Uart_SO/GPIO6)* 31(NC)* 32(TDO)* 34(RES_K3)* 42(SW_RX2)* 50(SW_BT)* 66(PCM_CLK)* 67(I2S_LRCLK)* 69(PCM_SYNC)* 70(TMS)* 71(I2S_MCLK)* 72(TCK)* 73(PCM_DIN)* 74(I2C_CLK)* 76(I2C_DAT)* 77(FM_A_IN_L)* 78(FM_A_OUT_L)* 81(W1_CTRL)* 84(FM_A_IN_R)* 85(FM_A_OUT_R)* 86(TDI)* 87(GPIO18/FM_host_wakeup)* 88(Uart_RTS)*; U169 12(NC)*

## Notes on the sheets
sheet 1
- ASPEN - Power
- No sequencing needed
- For A0 part use R69
  For B0 part use R68
- ?Ground trace join plane near ASPEN
- Enable V1P5_DDR_A after VCORE on
  and discharge v1p5_ddr_a rail quickly
- Enable 1.8V_OSC after VCORE on
- Temperature Sensor
- Enable 3.3V_USB after VCORE on
sheet 2
- Place across power plane split near WiFi signals
- Place across power plane split near WiFi signals
- Must bu outside shield
- New Antenova antenna
- Note: Need location from ID
- AW-NH387L 8787 WIFI
- BT/FM Audio
- FM Ctrl
- BT/FM Audio
- BT Ctrl
- Note: Need location from ID
- 8787 Power-On Sequence:
  3.3V/1.8V/SleepCLK -> RESET# High
- Start Time = 24ms
sheet 3
- use seltech MEO6027C85-382C1033
- HP_SENSE
- NO head phone jack
- use only ONE
  seltech GO2014C4Y8GN-1
  bestar  BMS2014P-11C-08H03 LF
- I2C linux address: 0x30
- 2.For SPKVDD_EN is high(3.3V) , SPKVDD will be enable
sheet 4
- Footprint 4Gb 512Mbytes MAX
  Part Used 1Gb 128MBytes
- SD/MMC connector
  FOR DEVELOPMENT USE
- SPI NOR FLASH
- Size: 128Mbit
- Close to pins
sheet 7
- All aspen LCD + Touch signals to bridge
- PIN SWAP OK
- D0 ............................ D17
- Use Molex FPC Jumper 2in 15015-0251
- SSP3_CLK
- SSP3_FRM
- SSP3_RXD
- SSP3_TXD
sheet 8
- ASPEN - MEMORY/FLASH/PANEL
- 18bit data for Panel matched to TIANMA TM022HDHT1
- DDR3 MEM
- short as possible
- Notes:
  Connect 240ohm 1% resistor to ground for
  CALPAD pin.
- Termination Resistor
- DDR_VREF; Close to pin
- RES close to ASPEN as possible
sheet 9
- Rechargeable Option
- For use with Lithium Ion 18650 batteries
- Tss = 1/4 Cshdn = ~1mS
- SHDN=L if VUSB_otg=5V
- DISABLE VBUS_OTG SHDN
  if USB_P_EN=high
- SHDN=L if VUSB_SER present
- SYSOFF
     LOW=ON
     HIGH=OFF*
- RT1
- R480 RISETA
     600R  ~1.0A
     1K    ~600mA
- RT2
- C378 Timer ~4Hr
- when controlled by software -
  EN2    EN1   EN0  VIN current
   L      L     H    90mA
   L      H     H    475mA
   H      L     H    1.5A
   H      H     H    Suspend
   X      X     L    Charger OFF
- need some driver migration
- ECO x: MAX17058 suymbol error fix
- ECO 5: charger thermister compensation fix
- I2C linux address: 0x33
